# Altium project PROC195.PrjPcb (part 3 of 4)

## Sheet PROC195_DAC.SchDoc
size 431 x 279 mm; SheetNumber: 14; SheetTotal: 20
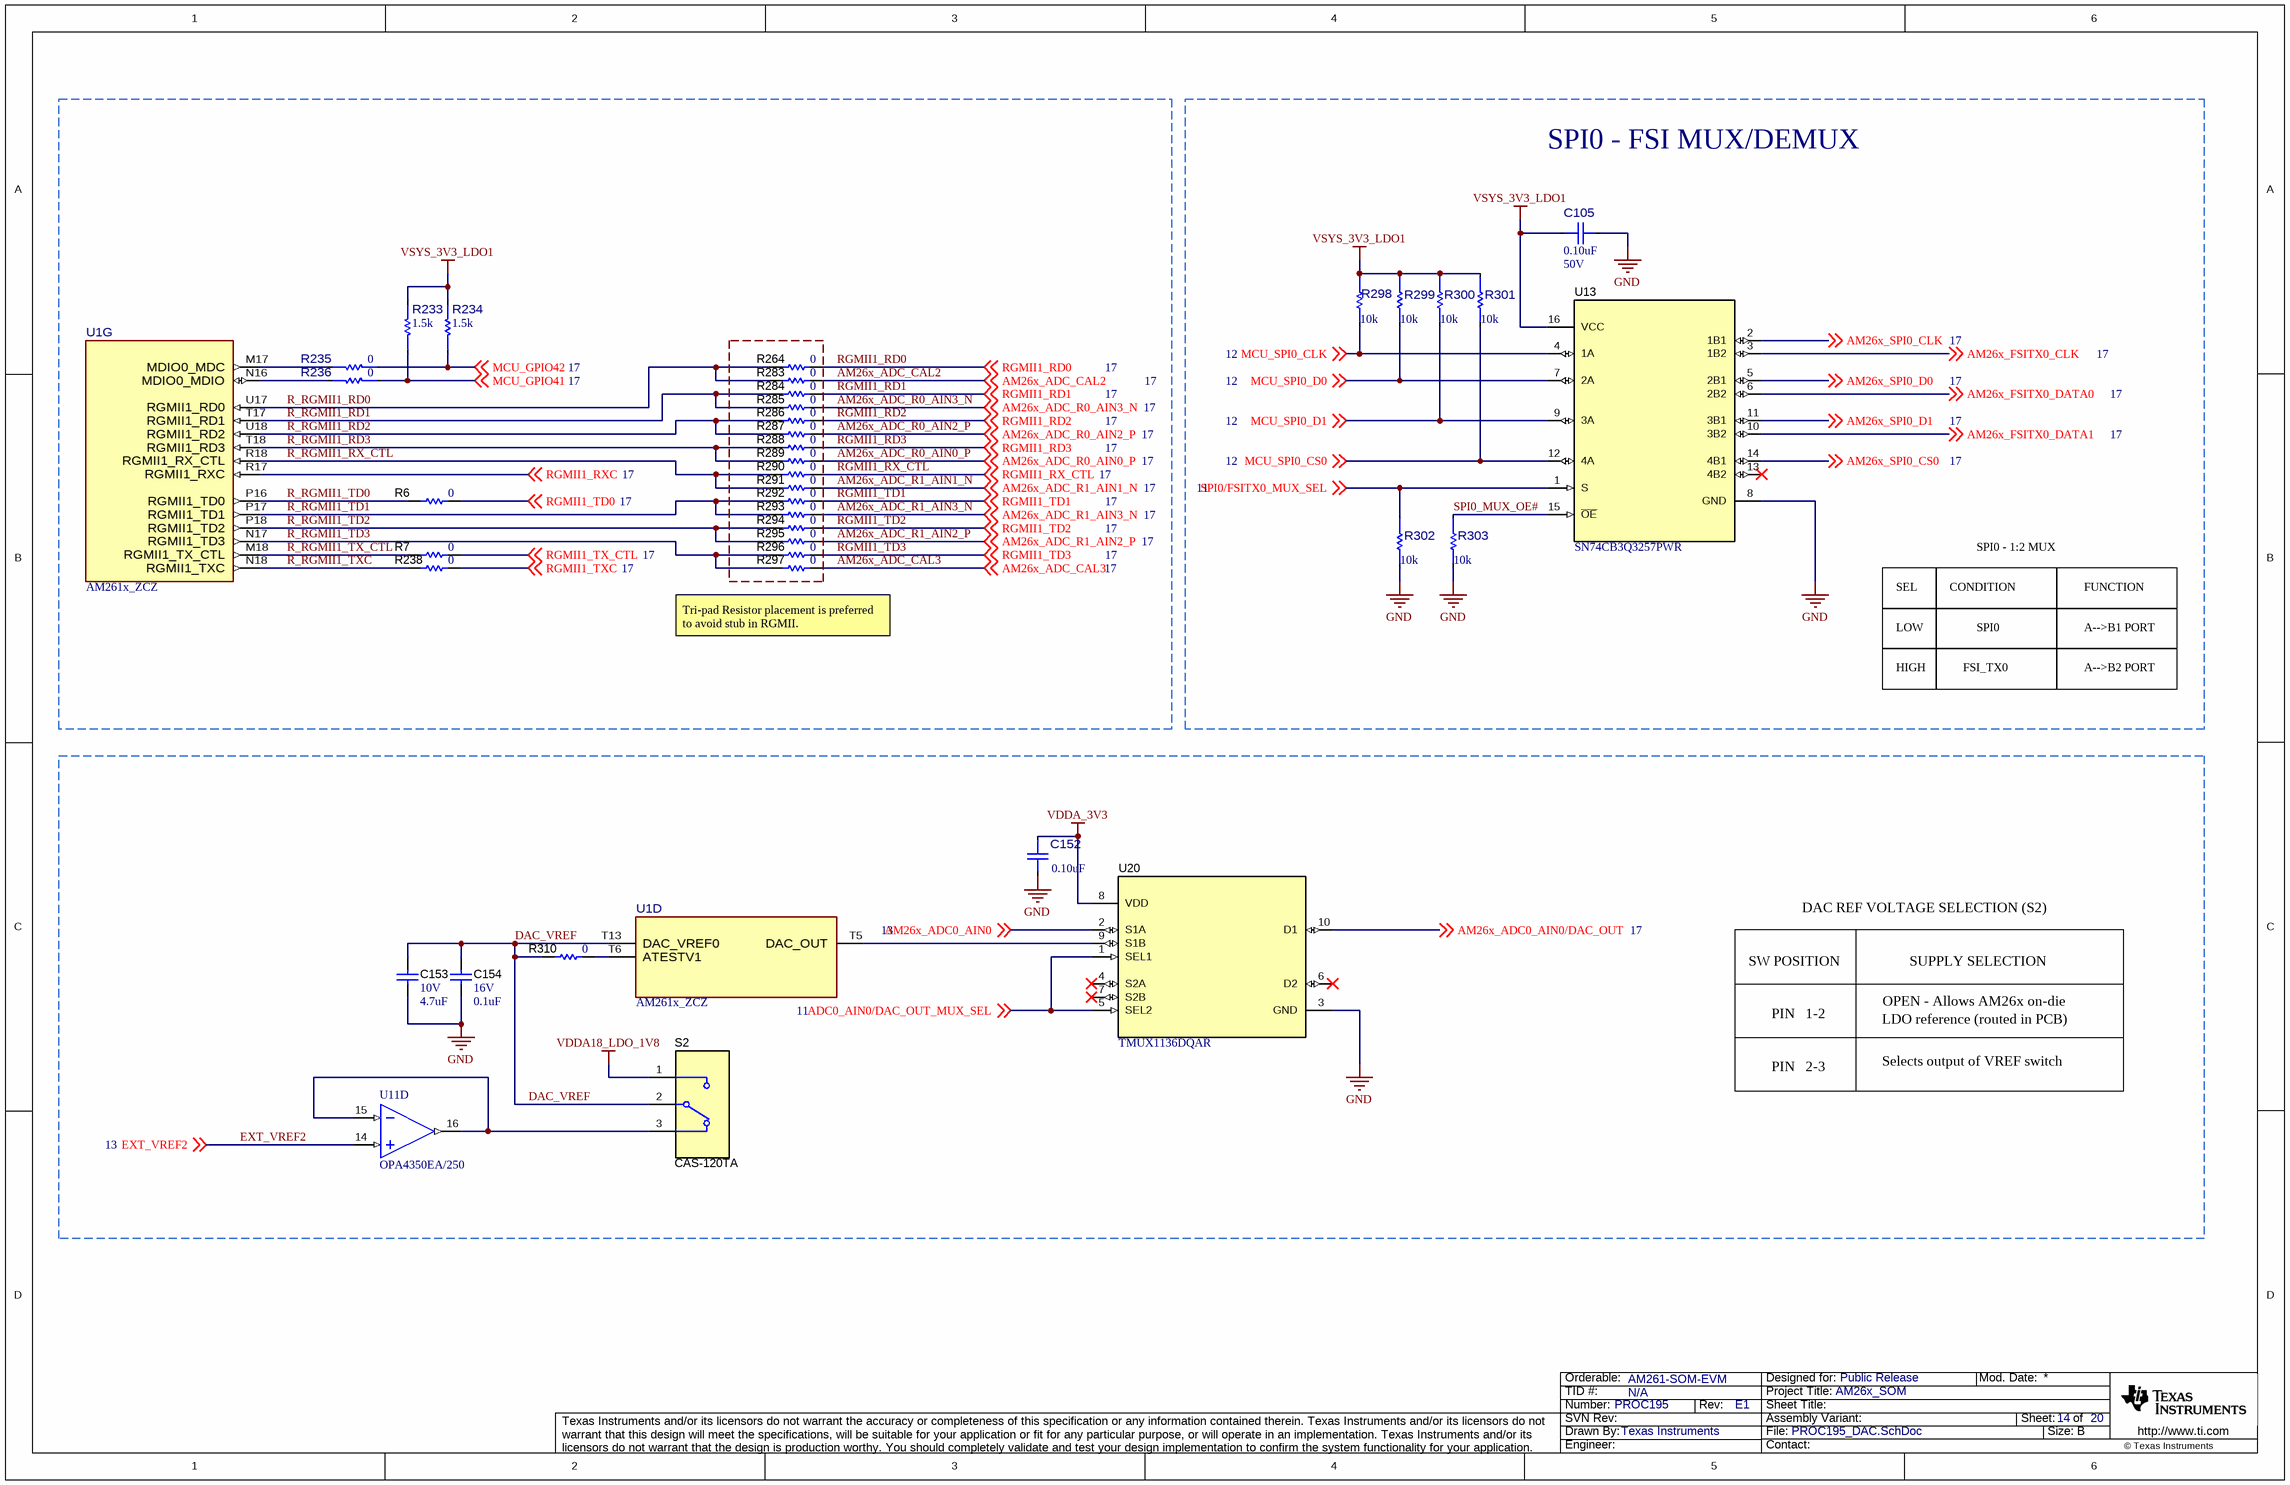
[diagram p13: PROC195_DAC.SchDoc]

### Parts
C105  ValueDisplayed: 0.10uF  VDC_V: 50V  [FP-GRM155R71H104KE14D_0402-MFG]  (hidden comment: GRM155R71H104KE14D)
C152  ValueDisplayed: 0.10uF  [FP-GRM155R71H104KE14D_0402-MFG]  (hidden comment: GRM155R71H104KE14D)
C153  VDC_V: 10V  ValueDisplayed: 4.7uF  [0402]  (hidden comment: GRM155R61A475MEAAD)
C154  VDC_V: 16V  ValueDisplayed: 0.1uF  [0201]  (hidden comment: GRM033Z71C104KE14D)
R6  ValueDisplayed: 0  [0201]  (hidden comment: ERJ-1GN0R00C)
R7  ValueDisplayed: 0  [0201]  (hidden comment: ERJ-1GN0R00C)
R233  value 1.5k  [FP-ERJ-2GEJ152X_0402-MFG]  (hidden comment: ERJ-2GEJ152X)
R234  value 1.5k  [FP-ERJ-2GEJ152X_0402-MFG]  (hidden comment: ERJ-2GEJ152X)
R235  value 0  [FP-ERJ-2GE0R00X_0402-MFG]  (hidden comment: ERJ-2GE0R00X)
R236  value 0  [FP-ERJ-2GE0R00X_0402-MFG]  (hidden comment: ERJ-2GE0R00X)
R238  ValueDisplayed: 0  [0201]  (hidden comment: ERJ-1GN0R00C)
R264  ValueDisplayed: 0  [0201]  (hidden comment: ERJ-1GN0R00C)
R283  ValueDisplayed: 0  [0201]  (hidden comment: ERJ-1GN0R00C)
R284  ValueDisplayed: 0  [0201]  (hidden comment: ERJ-1GN0R00C)
R285  ValueDisplayed: 0  [0201]  (hidden comment: ERJ-1GN0R00C)
R286  ValueDisplayed: 0  [0201]  (hidden comment: ERJ-1GN0R00C)
R287  ValueDisplayed: 0  [0201]  (hidden comment: ERJ-1GN0R00C)
R288  ValueDisplayed: 0  [0201]  (hidden comment: ERJ-1GN0R00C)
R289  ValueDisplayed: 0  [0201]  (hidden comment: ERJ-1GN0R00C)
R290  ValueDisplayed: 0  [0201]  (hidden comment: ERJ-1GN0R00C)
R291  ValueDisplayed: 0  [0201]  (hidden comment: ERJ-1GN0R00C)
R292  ValueDisplayed: 0  [0201]  (hidden comment: ERJ-1GN0R00C)
R293  ValueDisplayed: 0  [0201]  (hidden comment: ERJ-1GN0R00C)
R294  ValueDisplayed: 0  [0201]  (hidden comment: ERJ-1GN0R00C)
R295  ValueDisplayed: 0  [0201]  (hidden comment: ERJ-1GN0R00C)
R296  ValueDisplayed: 0  [0201]  (hidden comment: ERJ-1GN0R00C)
R297  ValueDisplayed: 0  [0201]  (hidden comment: ERJ-1GN0R00C)
R298  value 10k  [FP-RC0402JR-0710KL_0402-MFG]  (hidden comment: RC0402JR-0710KL)
R299  value 10k  [FP-RC0402JR-0710KL_0402-MFG]  (hidden comment: RC0402JR-0710KL)
R300  value 10k  [FP-RC0402JR-0710KL_0402-MFG]  (hidden comment: RC0402JR-0710KL)
R301  value 10k  [FP-RC0402JR-0710KL_0402-MFG]  (hidden comment: RC0402JR-0710KL)
R302  value 10k  [FP-RC0402JR-0710KL_0402-MFG]  (hidden comment: RC0402JR-0710KL)
R303  value 10k  [FP-RC0402JR-0710KL_0402-MFG]  (hidden comment: RC0402JR-0710KL)
R310  ValueDisplayed: 0  [0201]  (hidden comment: ERJ-1GN0R00C)
S2  CAS-120TA  [SW_CAS-120TA]
U1  AM261x_ZCZ  [ZCZ0324A-MFG]  (parts D,G of 13)
U11  OPA4350EA/250  [DBQ0016A_N]  (part D of 5)
U13  SN74CB3Q3257PWR  [PW0016A_L]
U20  TMUX1136DQAR  [DQA0010A]

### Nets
GND: C105.2 C152.2 C153.1 C154.1 R302.2 R303.2 U13.8(GND) U20.3(GND)
VDDA18_LDO_1V8: S2.1
VDDA_3V3: C152.1 U20.8(VDD)
VSYS_3V3_LDO1: C105.1 R233.2 R234.2 R298.1 R299.1 R300.1 R301.1 U13.16(VCC)
ADC0_AIN0/DAC_OUT_MUX_SEL: U20.1(SEL1) U20.5(SEL2) ; off-sheet ADC0_AIN0/DAC_OUT_MUX_SEL
AM26x_ADC0_AIN0: U20.2(S1A) ; off-sheet AM26x_ADC0_AIN0
AM26x_ADC0_AIN0/DAC_OUT: U20.10(D1) ; off-sheet AM26x_ADC0_AIN0/DAC_OUT
AM26x_ADC_CAL2: R283.2 ; off-sheet AM26x_ADC_CAL2
AM26x_ADC_CAL3: R297.2 ; off-sheet AM26x_ADC_CAL3
AM26x_ADC_R0_AIN0_P: R289.2 ; off-sheet AM26x_ADC_R0_AIN0_P
AM26x_ADC_R0_AIN2_P: R287.2 ; off-sheet AM26x_ADC_R0_AIN2_P
AM26x_ADC_R0_AIN3_N: R285.2 ; off-sheet AM26x_ADC_R0_AIN3_N
AM26x_ADC_R1_AIN1_N: R291.2 ; off-sheet AM26x_ADC_R1_AIN1_N
AM26x_ADC_R1_AIN2_P: R295.2 ; off-sheet AM26x_ADC_R1_AIN2_P
AM26x_ADC_R1_AIN3_N: R293.2 ; off-sheet AM26x_ADC_R1_AIN3_N
AM26x_FSITX0_CLK: U13.3(1B2) ; off-sheet AM26x_FSITX0_CLK
AM26x_FSITX0_DATA0: U13.6(2B2) ; off-sheet AM26x_FSITX0_DATA0
AM26x_FSITX0_DATA1: U13.10(3B2) ; off-sheet AM26x_FSITX0_DATA1
AM26x_SPI0_CLK: U13.2(1B1) ; off-sheet AM26x_SPI0_CLK
AM26x_SPI0_CS0: U13.14(4B1) ; off-sheet AM26x_SPI0_CS0
AM26x_SPI0_D0: U13.5(2B1) ; off-sheet AM26x_SPI0_D0
AM26x_SPI0_D1: U13.11(3B1) ; off-sheet AM26x_SPI0_D1
DAC_VREF: C153.2 C154.2 R310.1 S2.2 U1.T13(DAC_VREF0)
EXT_VREF2: U11.14(IN_D+) ; off-sheet EXT_VREF2
MCU_GPIO41: R233.1 R236.1 ; off-sheet MCU_GPIO41
MCU_GPIO42: R234.1 R235.1 ; off-sheet MCU_GPIO42
MCU_SPI0_CLK: R298.2 U13.4(1A) ; off-sheet MCU_SPI0_CLK
MCU_SPI0_CS0: R301.2 U13.12(4A) ; off-sheet MCU_SPI0_CS0
MCU_SPI0_D0: R299.2 U13.7(2A) ; off-sheet MCU_SPI0_D0
MCU_SPI0_D1: R300.2 U13.9(3A) ; off-sheet MCU_SPI0_D1
R_RGMII1_RD0: R264.1 R283.1 U1.U17(RGMII1_RD0)
R_RGMII1_RD1: R284.1 R285.1 U1.T17(RGMII1_RD1)
R_RGMII1_RD2: R286.1 R287.1 U1.U18(RGMII1_RD2)
R_RGMII1_RD3: R288.1 R289.1 U1.T18(RGMII1_RD3)
R_RGMII1_RX_CTL: R290.1 R291.1 U1.R18(RGMII1_RX_CTL)
R_RGMII1_TD0: R6.1 U1.P16(RGMII1_TD0)
R_RGMII1_TD1: R292.1 R293.1 U1.P17(RGMII1_TD1)
R_RGMII1_TD2: R294.1 R295.1 U1.P18(RGMII1_TD2)
R_RGMII1_TD3: R296.1 R297.1 U1.N17(RGMII1_TD3)
R_RGMII1_TX_CTL: R7.1 U1.M18(RGMII1_TX_CTL)
R_RGMII1_TXC: R238.1 U1.N18(RGMII1_TXC)
RGMII1_RD0: R264.2 ; off-sheet RGMII1_RD0
RGMII1_RD1: R284.2 ; off-sheet RGMII1_RD1
RGMII1_RD2: R286.2 ; off-sheet RGMII1_RD2
RGMII1_RD3: R288.2 ; off-sheet RGMII1_RD3
RGMII1_RX_CTL: R290.2 ; off-sheet RGMII1_RX_CTL
RGMII1_RXC: U1.R17(RGMII1_RXC) ; off-sheet RGMII1_RXC
RGMII1_TD0: R6.2 ; off-sheet RGMII1_TD0
RGMII1_TD1: R292.2 ; off-sheet RGMII1_TD1
RGMII1_TD2: R294.2 ; off-sheet RGMII1_TD2
RGMII1_TD3: R296.2 ; off-sheet RGMII1_TD3
RGMII1_TX_CTL: R7.2 ; off-sheet RGMII1_TX_CTL
RGMII1_TXC: R238.2 ; off-sheet RGMII1_TXC
SPI0/FSITX0_MUX_SEL: R302.1 U13.1(S) ; off-sheet SPI0/FSITX0_MUX_SEL
SPI0_MUX_OE#: R303.1 U13.15(~{OE})
NetR235_2: R235.2 U1.M17(MDIO0_MDC)
NetR236_2: R236.2 U1.N16(MDIO0_MDIO)
NetR310_2: R310.2 U1.T6(ATESTV1)
NetS2_3: S2.3 U11.15(IN_D-) U11.16(OUT_D)
NetU1_T5: U1.T5(DAC_OUT) U20.9(S1B)

Not connected (* = marked no-connect by the designer): U13 13(4B2)*; U20 4(S2A)* 6(D2)* 7(S2B)*

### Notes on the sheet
- SPI0 - FSI MUX/DEMUX
- SPI0 - 1:2 MUX
- Tri-pad Resistor placement is preferred to avoid stub in RGMII.
- SEL
- LOW
- CONDITION
- SPI0
- FUNCTION
- A-->B1 PORT
- HIGH
- FSI_TX0
- A-->B2 PORT
- SW POSITION
- DAC REF VOLTAGE SELECTION (S2)
- SUPPLY SELECTION
- PIN   1-2
- LDO reference (routed in PCB)
- OPEN - Allows AM26x on-die
- PIN   2-3
- Selects output of VREF switch

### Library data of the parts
C105 C152 = CMP-0096855-1: Chip Multilayer Ceramic Capacitors for General Purpose, 0402, 0.10uF, X7R, 15%, 10%, 50V; Manufacturer: Murata; SizeZ_mm: 0.55mm; Value: 100nF; AEC Qualified: No
C153 = CMP-0006582-2: CAP, CERM, 4.7 uF, 10 V, +/- 20%, X5R, 0402; Manufacturer: MuRata; TaMin_C: -55°C; Polarized: N; SizeAreaWB_mm2: 3; Value1: Unknown; U/M: EA; Value: 4.7uF; TaMax_C: 85°C; SizeZ_mm: 0.6; SizeX_mm: 1; SizeY_mm: 0.5; Cap_F: 4.7µF; AEC Category: Q200
C154 = CMP-0064970-1: CAP, CERM, 0.1 uF, 16 V,+/- 10%, X7R, 0201; Manufacturer: MuRata; TaMin_C: -55°C; Polarized: N; SizeAreaWB_mm2: 2.08; Value1: Unknown; U/M: EA; Value: 0.1uF; TaMax_C: 125°C; SizeZ_mm: 0.26; SizeX_mm: 0.6; SizeY_mm: 0.3; SizeArea_mm2: 0.18; Cap_F: 100nF; AEC Category: Q200
R6 R7 R238 R264 R283-R297 R310 = CMP-0065361-1: RES, 0, 5%, .05 W, AEC-Q200 Grade 0, 0201; Manufacturer: Panasonic; Power_W: 50mW; Green_Lifecycle: Not Set; TempCo: ppm/C; Value_Code: 0000; Green_REACh: Incomplete; U/M: EA; Value: 0; EIA_Code: E24; SizeX_mm: 0.6; SizeY_mm: 0.3; SizeZ_mm: 0.26; Value2: .05W; SizeArea_mm2: 0.18; AEC Qualified: Y; AEC Category: Q200
R233 R234 = CMP-0042990-1: Res Thick Film 0402 1.5K Ohm 5% 1/10W ±200ppm/°C Molded SMD Punched Carrier T/R; Manufacturer: Panasonic; AEC Grade: Grade 0; AEC Qualified: Yes; Power_W: 100mW; SizeZ_mm: 0.4mm; VDC_V: 50V; Category 5A00970A6D5C81C7: Uncategorized; Category 5C6A91606D4187Ad: Resistors; Category 7542B8484461Ae85: Passive Components; Category Cd01000Bfc2916C6: Single Components
R235 R236 = CMP-0002710-1: 0 Ohms Jumper Chip Resistor 0402 (1005 Metric) Automotive AEC-Q200 Thick Film; Manufacturer: Panasonic; AEC Grade: Grade 0; AEC Qualified: Yes; SizeZ_mm: 0.4mm; Power: 100mW
R298-R303 = CMP-0094798-1: Res Thick Film 0402 10K Ohm 5% 0.063W(1/16W) ±100ppm/C Pad SMD T/R; Manufacturer: YAGEO; AEC Qualified: No; Category Cd01000Bfc2916C6: Single Components; SizeZ_mm: 0.4mm; VDC_V: 50V; Category 5C6A91606D4187Ad: Resistors; TempCo: 100ppm/°C; Power_W: 63mW; Category 7542B8484461Ae85: Passive Components
S2 = CMP-0002139-2: Switch, Slide, SPDT  100mA, SMT; Manufacturer: Copal Electronics; CurrentRating_mA: 100A; SwitchFunction: On-On; VDC_V: 6V; PositionCount: 1
U1 = CMP-0121930-1: Manufacturer: Texas Instruments; SizeZ_mm: 1.4mm; Standoff Height: 0.35mm
U11 = CMP-0041147-1: High-Speed, Single-Supply, Rail-to-Rail Operational Amplifier MicroAmplifier(TM) Series, 2.7 to 5.5 V, -55 to 150 degC, 16-pin SOP (DBQ16), Green (RoHS & no Sb/Br); Manufacturer: Texas Instruments; Number of Channels: 4; Vio (25C)(Max)(mV): 0.5; Total Supply Voltage(Min)(+5V is 5, +/-5V is 10): 2.7; Slew Rate(Typ)(V/us): 22; Total Supply Voltage(Max)(+5V is 5, +/-5V is 10): 5.5; Iq per channel(Max)(mA): 7.5; Vn at 1kHz(Typ)(nV/rtHz): 18; Sub Family: Low Input Bias Current Amp (<=10pA), Low Offset Voltage Amplifier (<=500uV), Low Supply Voltage Amplifier (<=2.7V), Precision Amplifier; IIB(Max)(pA): 10; CMRR(Min)(dB): 66
U13 = CMP-0076540-1: 4-Bit One-of-2 FET Multiplexer/Demultiplexer 2.5-V/3.3-V Low-Voltage, High-Bandwidth Bus Switch, PW0016A (TSSOP-16); Manufacturer: Texas Instruments; SizeAreaWB_mm2: 58.8; SizeArea_mm2: 32.0; SizeZ_mm: 1.2; SizeY_mm: 5.0; U/M: EA; CompType: IC; SizeX_mm: 6.4
U20 = CMP-0860454-1: 5-V Low-Leakage-Current, 2:1, 2-Channel Precision Analog Switch, DQA0010A (USON-10); Manufacturer: Texas Instruments; SizeZ_mm: 0.55; SizeX_mm: 1; AEC Category: Q200; SizeArea_mm2: 2.5; AEC Qualified: N; SizeAreaWB_mm2: 7; Rating: Catalog; CompType: IC

## Sheet PROC195_CLK_LED_CURRENT_MON_TEMP_CONN.SchDoc
size 431 x 279 mm; DocumentNumber: 7; SheetNumber: 15; SheetTotal: 20; PageSetup: Record=PageOptions¦CenterHorizontal=True¦CenterVertical=True¦PrintScale=1.00¦XCorrection=1.00¦YCorrection=1.00¦PrintKind=0¦BorderSize=5000000¦LeftOffset=0¦BottomOffset=0¦Orientation=2¦PaperLength=1000¦PaperWidth=1000¦Scale=100¦PaperSource=15¦PrintQuality=600¦MediaType=1¦DitherType=10¦PaperKind=Letter¦PrintScaleMode=1
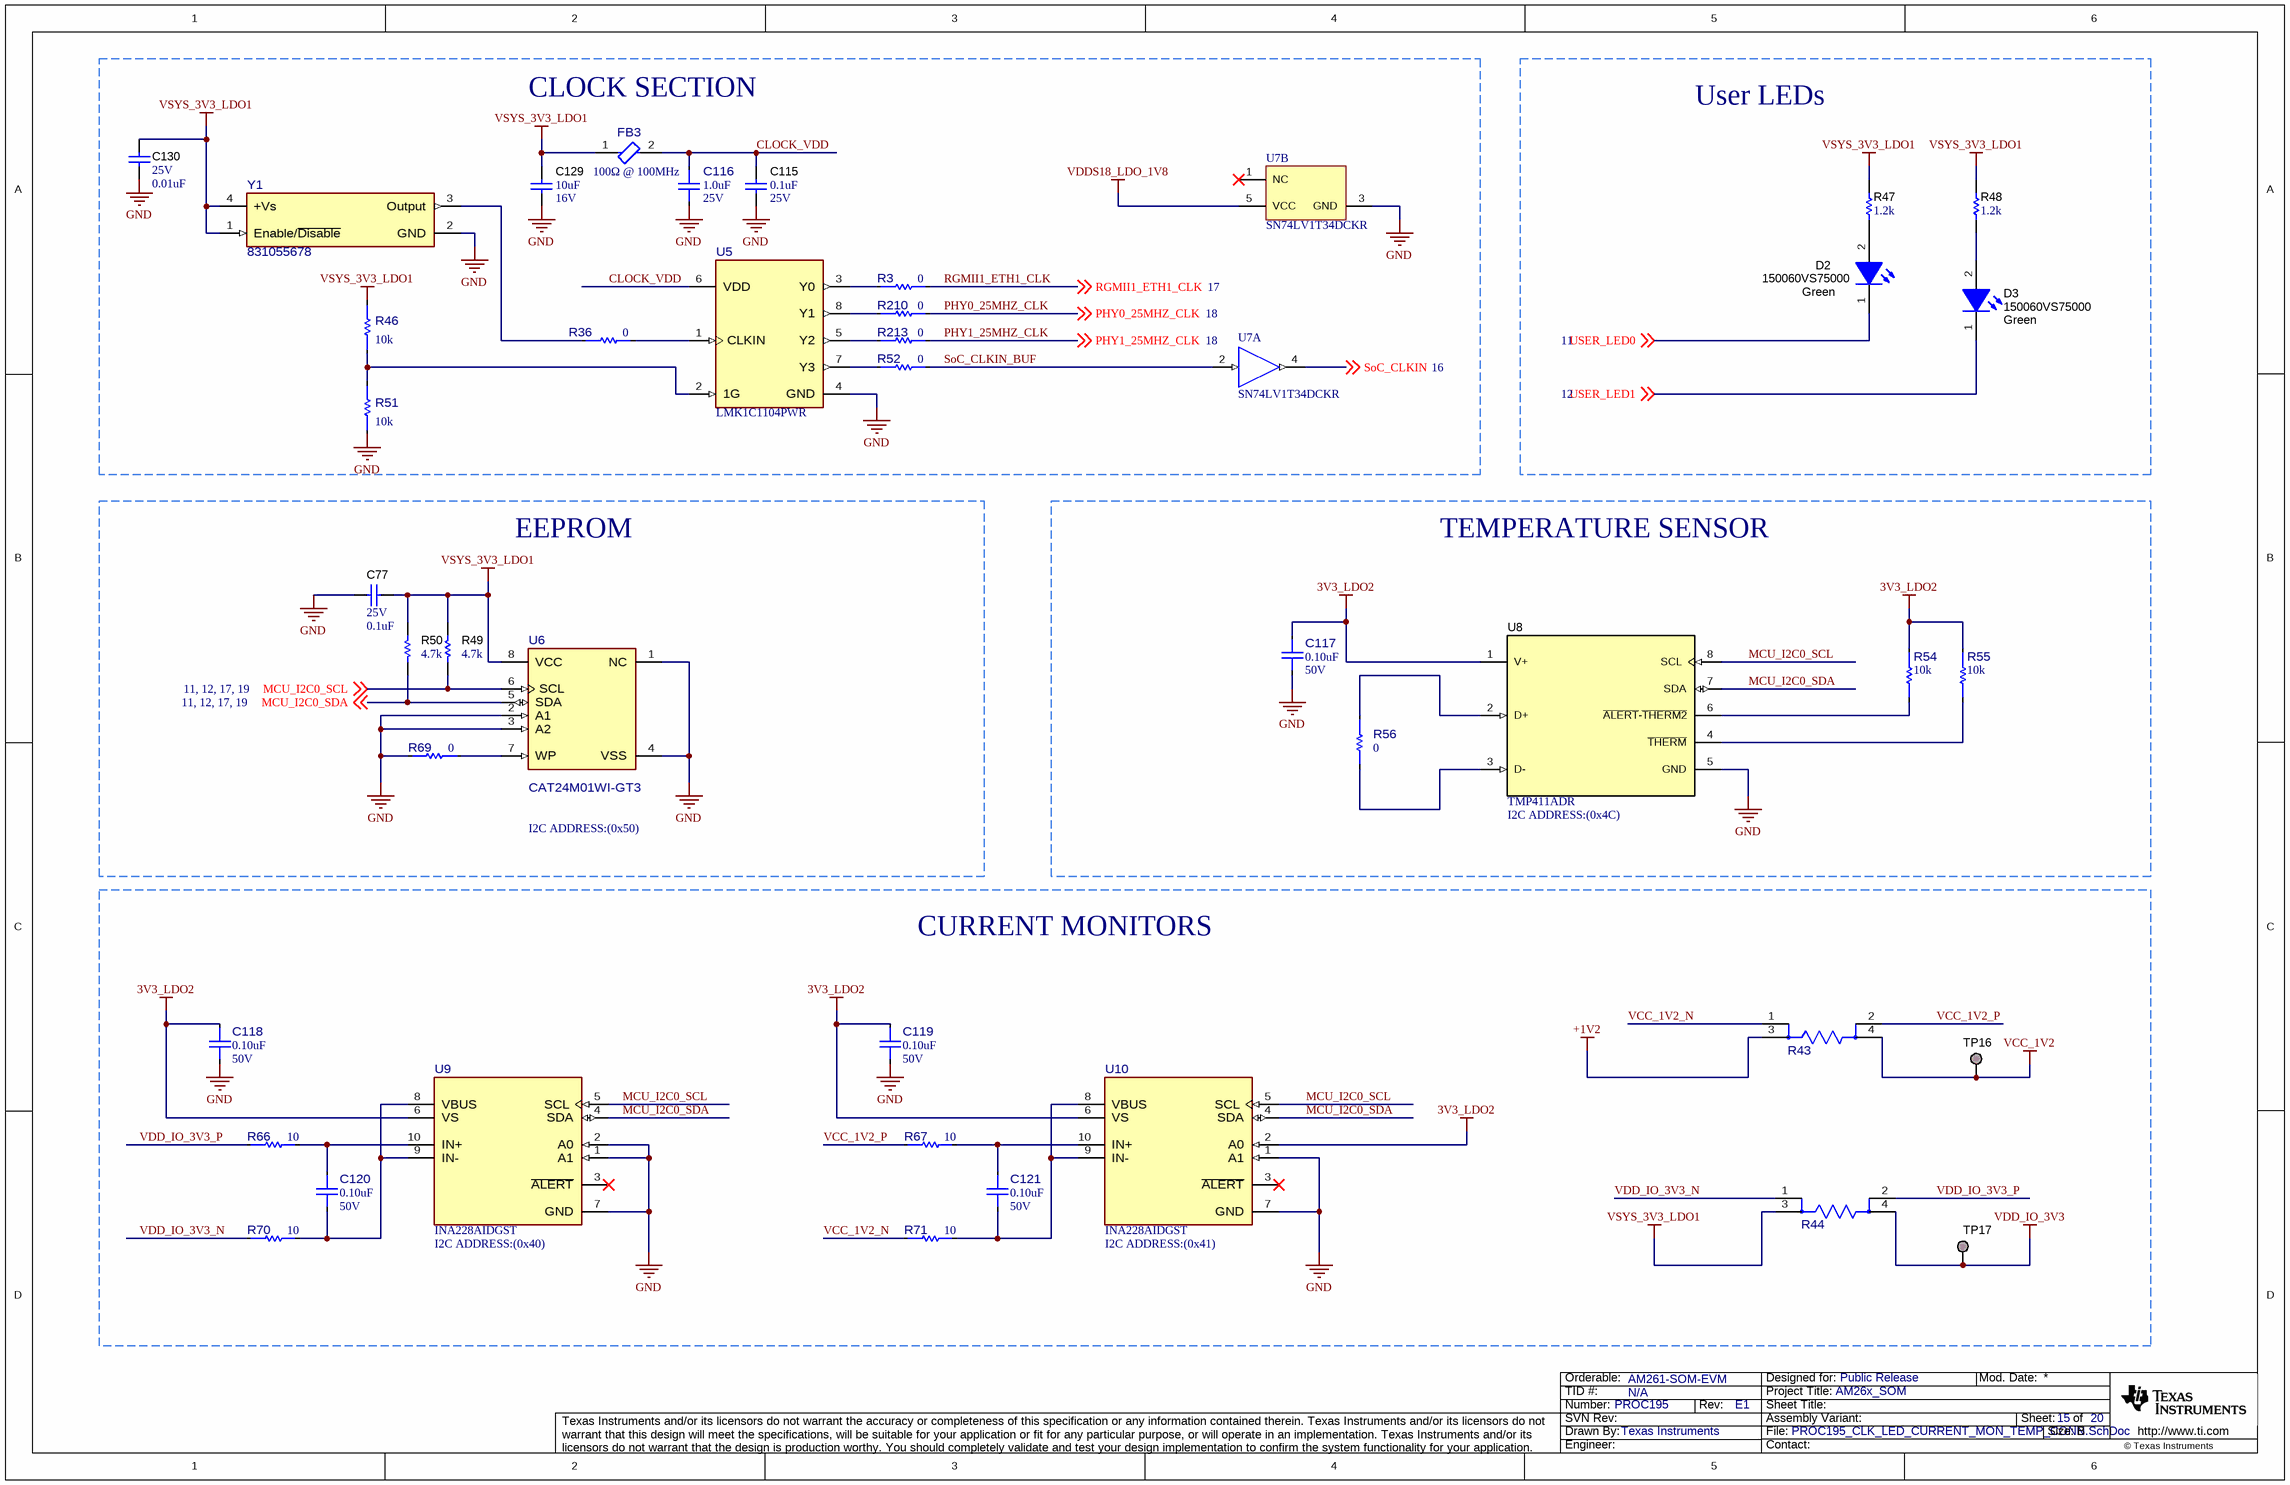
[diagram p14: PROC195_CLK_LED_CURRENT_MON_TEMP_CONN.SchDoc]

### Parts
C77  VDC_V: 25V  ValueDisplayed: 0.1uF  [0402]  (hidden comment: GRM155R71E104KE14D)
C115  VDC_V: 25V  ValueDisplayed: 0.1uF  [0402]  (hidden comment: GRM155R71E104KE14D)
C116  ValueDisplayed: 1.0uF  VDC_V: 25V  [FP-GRM155C81E105KE11D_0402-MFG]  (hidden comment: GRM155C81E105KE11D)
C117  ValueDisplayed: 0.10uF  VDC_V: 50V  [FP-GRM155R71H104KE14D_0402-MFG]  (hidden comment: GRM155R71H104KE14D)
C118  ValueDisplayed: 0.10uF  VDC_V: 50V  [FP-GRM155R71H104KE14D_0402-MFG]  (hidden comment: GRM155R71H104KE14D)
C119  ValueDisplayed: 0.10uF  VDC_V: 50V  [FP-GRM155R71H104KE14D_0402-MFG]  (hidden comment: GRM155R71H104KE14D)
C120  ValueDisplayed: 0.10uF  VDC_V: 50V  [FP-GRM155R71H104KE14D_0402-MFG]  (hidden comment: GRM155R71H104KE14D)
C121  ValueDisplayed: 0.10uF  VDC_V: 50V  [FP-GRM155R71H104KE14D_0402-MFG]  (hidden comment: GRM155R71H104KE14D)
C129  VDC_V: 16V  ValueDisplayed: 10uF  [0603]  (hidden comment: GRM188R61C106MAALD)
C130  VDC_V: 25V  ValueDisplayed: 0.01uF  [0402]  (hidden comment: GCM155R71E103KA37D)
D2  150060VS75000  value Green  [WL-SMCW_GREEN]
D3  150060VS75000  value Green  [WL-SMCW_GREEN]
FB3  Impedance At Frequency: 100Ω @ 100MHz  [FP-BLM18EG101TN1D_0603-MFG]  (hidden comment: BLM18EG101TN1D)
R3  value 0  [FP-ERJ-2GE0R00X_0402-MFG]  (hidden comment: ERJ-2GE0R00X)
R36  value 0  [FP-ERJ-2GE0R00X_0402-MFG]  (hidden comment: ERJ-2GE0R00X)
R43  FC4L16R010FER  [FP-FC4L16R010FER_0306-MFG]  (value not drawn)
R44  FC4L16R010FER  [FP-FC4L16R010FER_0306-MFG]  (value not drawn)
R46  value 10k  [FP-RC0402JR-0710KL_0402-MFG]  (hidden comment: RC0402JR-0710KL)
R47  ValueDisplayed: 1.2k  [0402]  (hidden comment: CRCW04021K20JNED)
R48  ValueDisplayed: 1.2k  [0402]  (hidden comment: CRCW04021K20JNED)
R49  value 4.7k  [0402]  (hidden comment: CRCW04024K70JNED)
R50  value 4.7k  [0402]  (hidden comment: CRCW04024K70JNED)
R51  value 10k  [FP-RC0402JR-0710KL_0402-MFG]  (hidden comment: RC0402JR-0710KL)
R52  value 0  [FP-ERJ-2GE0R00X_0402-MFG]  (hidden comment: ERJ-2GE0R00X)
R54  value 10k  [FP-RC0402JR-0710KL_0402-MFG]  (hidden comment: RC0402JR-0710KL)
R55  value 10k  [FP-RC0402JR-0710KL_0402-MFG]  (hidden comment: RC0402JR-0710KL)
R56  value 0  [FP-ERJ-2GE0R00X_0402-MFG]  (hidden comment: ERJ-2GE0R00X)
R66  value 10  [FP-RC0402FR-0710RL_0402-MFG]  (hidden comment: RC0402FR-0710RL)
R67  value 10  [FP-RC0402FR-0710RL_0402-MFG]  (hidden comment: RC0402FR-0710RL)
R69  value 0  [FP-ERJ-2GE0R00X_0402-MFG]  (hidden comment: ERJ-2GE0R00X)
R70  value 10  [FP-RC0402FR-0710RL_0402-MFG]  (hidden comment: RC0402FR-0710RL)
R71  value 10  [FP-RC0402FR-0710RL_0402-MFG]  (hidden comment: RC0402FR-0710RL)
R210  value 0  [FP-ERJ-2GE0R00X_0402-MFG]  (hidden comment: ERJ-2GE0R00X)
R213  value 0  [FP-ERJ-2GE0R00X_0402-MFG]  (hidden comment: ERJ-2GE0R00X)
TP16  TESTPOINT  [TP_25MIL-SMT]  (value not drawn)  (no BOM)
TP17  TESTPOINT  [TP_25MIL-SMT]  (value not drawn)  (no BOM)
U5  LMK1C1104PWR  [PW0008A-MFG]
U6  CAT24M01WI-GT3  [FP-CAT24M01WI-GT3_SOIC8-IPC_C]
U7  SN74LV1T34DCKR  [DCK0005A_N]  (parts A,B of 2)
U8  TMP411ADR  [D0008A_N]
U9  INA228AIDGST  [DGS0010A-MFG]
U10  INA228AIDGST  [DGS0010A-MFG]
Y1  831055678  [FP-831055678_SMT_OSC_3MM2_2MM5-MFG]

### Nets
3V3_LDO2: C117.1 C118.1 C119.1 R54.1 R55.1 U8.1(V+) U9.6(VS) U10.2(A0) U10.6(VS)
+1V2: R43.3(1_I)
GND: C77.2 C115.2 C116.2 C117.2 C118.2 C119.2 C129.2 C130.1 R51.1 R69.2 U5.4(GND) U6.1(NC) U6.2(A1) U6.3(A2) U6.4(VSS) U7.3(GND) U8.5(GND) U9.1(A1) U9.2(A0) U9.7(GND) U10.1(A1) U10.7(GND) Y1.2(GND)
VCC_1V2: R43.4(2_I) TP16.1
VDD_IO_3V3: R44.4(2_I) TP17.1
VDDS18_LDO_1V8: U7.5(VCC)
VSYS_3V3_LDO1: C77.1 C129.1 C130.2 FB3.1 R44.3(1_I) R46.2 R47.2 R48.2 R49.2 R50.2 U6.8(VCC) Y1.1(Enable/~{Disable}) Y1.4(+Vs)
CLOCK_VDD: C115.1 C116.1 FB3.2 U5.6(VDD)
MCU_I2C0_SCL: R49.1 U6.6(SCL) U8.8(SCL) U9.5(SCL) U10.5(SCL) ; off-sheet MCU_I2C0_SCL
MCU_I2C0_SDA: R50.1 U6.5(SDA) U8.7(SDA) U9.4(SDA) U10.4(SDA) ; off-sheet MCU_I2C0_SDA
PHY0_25MHZ_CLK: R210.2 ; off-sheet PHY0_25MHZ_CLK
PHY1_25MHZ_CLK: R213.2 ; off-sheet PHY1_25MHZ_CLK
RGMII1_ETH1_CLK: R3.2 ; off-sheet RGMII1_ETH1_CLK
SoC_CLKIN: U7.4(Y) ; off-sheet SoC_CLKIN
SoC_CLKIN_BUF: R52.2 U7.2(A)
USER_LED0: D2.1(K) ; off-sheet USER_LED0
USER_LED1: D3.1(K) ; off-sheet USER_LED1
VCC_1V2_N: R43.1(1_V) R71.1
VCC_1V2_P: R43.2(2_V) R67.1
VDD_IO_3V3_N: R44.1(1_V) R70.1
VDD_IO_3V3_P: R44.2(2_V) R66.1
NetC120_1: C120.1 R66.2 U9.10(IN+)
NetC120_2: C120.2 R70.2 U9.8(VBUS) U9.9(IN-)
NetC121_1: C121.1 R67.2 U10.10(IN+)
NetC121_2: C121.2 R71.2 U10.8(VBUS) U10.9(IN-)
NetD2_2: D2.2(A) R47.1
NetD3_2: D3.2(A) R48.1
NetR3_1: R3.1 U5.3(Y0)
NetR36_1: R36.1 Y1.3(Output)
NetR36_2: R36.2 U5.1(CLKIN)
NetR46_1: R46.1 R51.2 U5.2(1G)
NetR52_1: R52.1 U5.7(Y3)
NetR54_2: R54.2 U8.6(~{ALERT}-~{THERM2})
NetR55_2: R55.2 U8.4(~{THERM})
NetR56_1: R56.1 U8.2(D+)
NetR56_2: R56.2 U8.3(D-)
NetR69_1: R69.1 U6.7(WP)
NetR210_1: R210.1 U5.8(Y1)
NetR213_1: R213.1 U5.5(Y2)

Not connected (* = marked no-connect by the designer): U7 1(NC)*; U9 3(~{ALERT})*; U10 3(~{ALERT})*

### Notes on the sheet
- CLOCK SECTION
- User LEDs
- EEPROM
- TEMPERATURE SENSOR
- I2C ADDRESS:(0x50)
- (near U8) I2C ADDRESS:(0x4C)
- CURRENT MONITORS
- (near U9) I2C ADDRESS:(0x40)
- (near U10) I2C ADDRESS:(0x41)

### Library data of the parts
C77 C115 = CMP-0006659-2: CAP, CERM, 0.1 uF, 25 V, +/- 10%, X7R, 0402; Manufacturer: MuRata; TaMin_C: -55°C; Polarized: N; SizeAreaWB_mm2: 3; Value1: Unknown; U/M: EA; Value: 0.1uF; TaMax_C: 125°C; SizeZ_mm: 0.6; SizeX_mm: 1; SizeY_mm: 0.5; Cap_F: 100nF; AEC Category: Q200
C116 = CMP-0121658-2: Chip Multilayer Ceramic Capacitors for General Purpose, 0402, 1.0uF, X6S, 22%, 10%, 25V; Manufacturer: Murata; AEC Qualified: No; Cap_F: 1µF; SizeZ_mm: 0.6mm; Value: 1µF
C117-C121 = CMP-0096855-1: as C105 on sheet PROC195_DAC
C129 = CMP-0007336-5: CAP, CERM, 10 uF, 16 V, +/- 20%, X5R, 0603; Manufacturer: MuRata; TaMin_C: -55°C; Polarized: N; SizeAreaWB_mm2: 4.68; Value1: Unknown; U/M: EA; Value: 10uF; TaMax_C: 85°C; SizeZ_mm: 1; SizeX_mm: 1.6; SizeY_mm: 0.8; SizeArea_mm2: 1.28; Cap_F: 10µF; AEC Category: Q200
C130 = CMP-0006352-2: CAP, CERM, 0.01 uF, 25 V, +/- 10%, X7R, 0402; Manufacturer: MuRata; TaMin_C: -55°C; Polarized: N; SizeAreaWB_mm2: 3; Value1: Unknown; U/M: EA; Value: 0.01uF; TaMax_C: 125°C; SizeZ_mm: 0.6; SizeX_mm: 1; SizeY_mm: 0.5; Cap_F: 10nF; AEC Category: Q200
D2 D3 = CMP-0002894-2: LED, Green, SMD; Manufacturer: Wurth Elektronik; Io_A: 20mA; Value1: W; Vf_V: 2V; Type: AlInGaP
FB3 = CMP-0122093-1: Chip Ferrite Bead, 0603, 100Ω @ 100MHz, 25%, 0.045Ω, 2A; Manufacturer: Murata; DCR_ohm: 45m; SizeZ_mm: 0.65mm; AEC Qualified: No
R3 R36 R52 R56 R69 R210 R213 = CMP-0002710-1: 0 Ohms Jumper Chip Resistor 0402 (1005 Metric) Automotive AEC-Q200 Thick Film; Manufacturer: Panasonic; SizeZ_mm: 0.4mm; AEC Qualified: Yes; AEC Grade: Grade 0; Power: 100mW
R43 R44 = CMP-0122058-1: Res Metal Foil 0306 0.01 Ohm 1% 0.25W(1/4W) ±50ppm/C Epoxy Resin Wide Terminal SMD T/R; Manufacturer: Ohmite; AEC Qualified: No; Power_W: 250mW; Res_ohm: 10m; SizeZ_mm: 0.7mm; TempCo: 50ppm/°C; Value: 10m
R46 R51 = CMP-0094798-1: Res Thick Film 0402 10K Ohm 5% 0.063W(1/16W) ±100ppm/C Pad SMD T/R; Manufacturer: YAGEO; Power_W: 63mW; TempCo: 100ppm/°C; SizeZ_mm: 0.4mm; AEC Qualified: No; VDC_V: 50V; Category Cd01000Bfc2916C6: Single Components; Category 5C6A91606D4187Ad: Resistors; Category 7542B8484461Ae85: Passive Components
R47 R48 = CMP-0026854-5: RES, 1.2 k, 5%, 0.063 W, AEC-Q200 Grade 0, 0402; Manufacturer: Vishay-Dale; Power_W: 63mW; TempCo: 200 ppm/C; Value_Code: 1k20; Value: 1.2k; EIA_Code: E24; SizeX_mm: 1; SizeY_mm: 0.5; SizeZ_mm: 0.6; Value2: 0.063W; AEC Qualified: Y; VDC_V: 50V; AEC Category: Q200; AEC Grade: 0
R49 R50 = CMP-0026938-5: RES, 4.7 k, 5%, 0.063 W, AEC-Q200 Grade 0, 0402; Manufacturer: Vishay-Dale; Power_W: 63mW; TempCo: 200 ppm/C; Value_Code: 4k70; SizeX_mm: 1; SizeY_mm: 0.5; SizeZ_mm: 0.6; Value2: 0.063W; AEC Qualified: Y; AEC Grade: 0; AEC Category: Q200; EIA_Code: E24; VDC_V: 50V
R54 R55 = CMP-0094798-1: as R298-R303 on sheet PROC195_DAC
R66 R67 R70 R71 = CMP-0122043-1: Res General Purpose Thick Film 0402 10 Ohm 1% 1/16W ±200ppm/°C Molded SMD Paper T/R; Manufacturer: Yageo; AEC Qualified: No; Power_W: 63mW; SizeZ_mm: 0.4mm; VDC_V: 50V
TP16 TP17 = CMP-0078143-3: TEST POINT.  No entry in BOM.
U5 = CMP-0096980-1: 1.8-V, 2.5-V, and 3.3-V LVCMOS Clock Buffer Family; Manufacturer: Texas Instruments; Logic Function: Non-Inverting; TaMax_C: +125°C; TJmax_C: +150°C; Max Supply Voltage: 3.465V; Number Of Elements: 5; TaMin_C: -40°C; Nominal Supply Current: 25-33000uA; Number Of Outputs: 4; Number Of Inputs: 1; AEC Qualified: No; Min Supply Voltage: 1.71V; SizeZ_mm: 1.2mm; Standoff Height: 0.05mm; Propagation Delay: 1.5ns
U6 = CMP-0122130-1: EEPROM Serial-I2C 1M-bit 128K x 8 2.5V/3.3V/5V 8-Pin SOIC N T/R; Manufacturer: ON Semi; SizeZ_mm: 1.75mm; Access Time: 0.4us; AEC Qualified: No; Frequency_Fixed: 1MHz; Interface: I2C; Max Supply Voltage: 5.5V; Memory Size: 1Mbits; Min Supply Voltage: 1.8V; Nominal Supply Current: 1-5mA; Standoff Height: 0.1mm; TaMax_C: +85°C; TaMin_C: -40°C; TJmax_C: +150°C
U7 = CMP-0051718-3: Single Power Supply BUFFER Logic Level Shifter (no enable), DCK0005A (SOT-SC70-5); Manufacturer: Texas Instruments; 3-State Output: Yes; Sub-Family: Non-Inverting Buffer/Driver; Rating: Catalog; ICC @ Nom Voltage(Max)(mA): 0.01; Logic: True; tpd @ Nom Voltage(Max)(ns): 14.5,9.5,8.0,6.5; Output Type: CMOS; VCC(Max)(V): 5.5; Voltage(Nom)(V): 1.8,2.5,3.3,5.5; Bits(#): 1; Output Drive (IOL/IOH)(Max)(mA): 8/-8; F @ Nom Voltage(Max)(Mhz): 50; Special Features: 1.8V to 3.3V Up Translation,3.3V to 1.8V Down Translation,5V Input Tolerant; Input Type: TTL; Technology Family: LV1T; VCC(Min)(V): 1.6; AEC Category: Q200; AEC Qualified: N; CompType: IC; SizeAreaWB_mm2: 9.3; SizeArea_mm2: 4.2; SizeX_mm: 2.1; SizeY_mm: 2.0; SizeZ_mm: 1.1
U8 = CMP-0078516-1: Remote and Local Temperature Sensor with N-Factor and Series-R Correction in MSOP-8, D0008A (SOIC-8); Alternate Manufacturer: Texas Instruments; SizeAreaWB_mm2: 56.58; SizeZ_mm: 1.75; SizeX_mm: 4.9; SizeY_mm: 6.2; SizeArea_mm2: 30.38; CompType: IC; AEC Qualified: N; AEC Category: Q200
U9 U10 = CMP-0098432-1: Current Sense Amplifier 1 Circuit 10-VSSOP; Manufacturer: Texas Instruments; SizeZ_mm: 1.1mm; AEC Qualified: No; Input Bias Current: 0.01uA; Input Offset Voltage: 1mV; Max Supply Voltage: 5.5V; Min Supply Voltage: 2.7V; Nominal Supply Current: 640uA; Number Of Channels: 1; Standoff Height: 0.05mm; TaMax_C: +125°C; TaMin_C: -40°C; TJmax_C: +150°C
Y1 = CMP-0122114-1: 25 MHz XO (Standard) CMOS Oscillator 3.3V Standby (Power Down) 4-SMD, No Lead; Manufacturer: Wurth Electronics; Frequency Stability: 25ppm; Frequency_Fixed: 25MHz; SizeZ_mm: 1.2mm; Load Capacitance: 15pF; Max Supply Current: 12mA; Max Supply Voltage: 3.63V; Min Supply Voltage: 2.97V

## Sheet PROC195_RESET_CIRCUIT.SchDoc
size 431 x 279 mm; Date: Not shown in title block; ApprovedBy: Not shown in title block; CheckedBy: Not shown in title block; Author: Not shown in title block; CompanyName: Not shown in title block; Engineer: Not shown in title block; Organization: Not shown in title block; Address1: Not shown in title block; Address2: Not shown in title block; Address3: Not shown in title block; Address4: Not shown in title block; DocumentNumber: 1; Revision: Use project parameter SCH_Rev; SheetNumber: 16; SheetTotal: 20; PageSetup: Record=PageOptions¦CenterHorizontal=True¦CenterVertical=True¦PrintScale=1.00¦XCorrection=1.00¦YCorrection=1.00¦PrintKind=0¦BorderSize=5000000¦LeftOffset=0¦BottomOffset=0¦Orientation=2¦PaperLength=1000¦PaperWidth=1000¦Scale=100¦PaperSource=15¦PrintQuality=600¦MediaType=1¦DitherType=10¦PaperKind=Letter¦PrintScaleMode=1
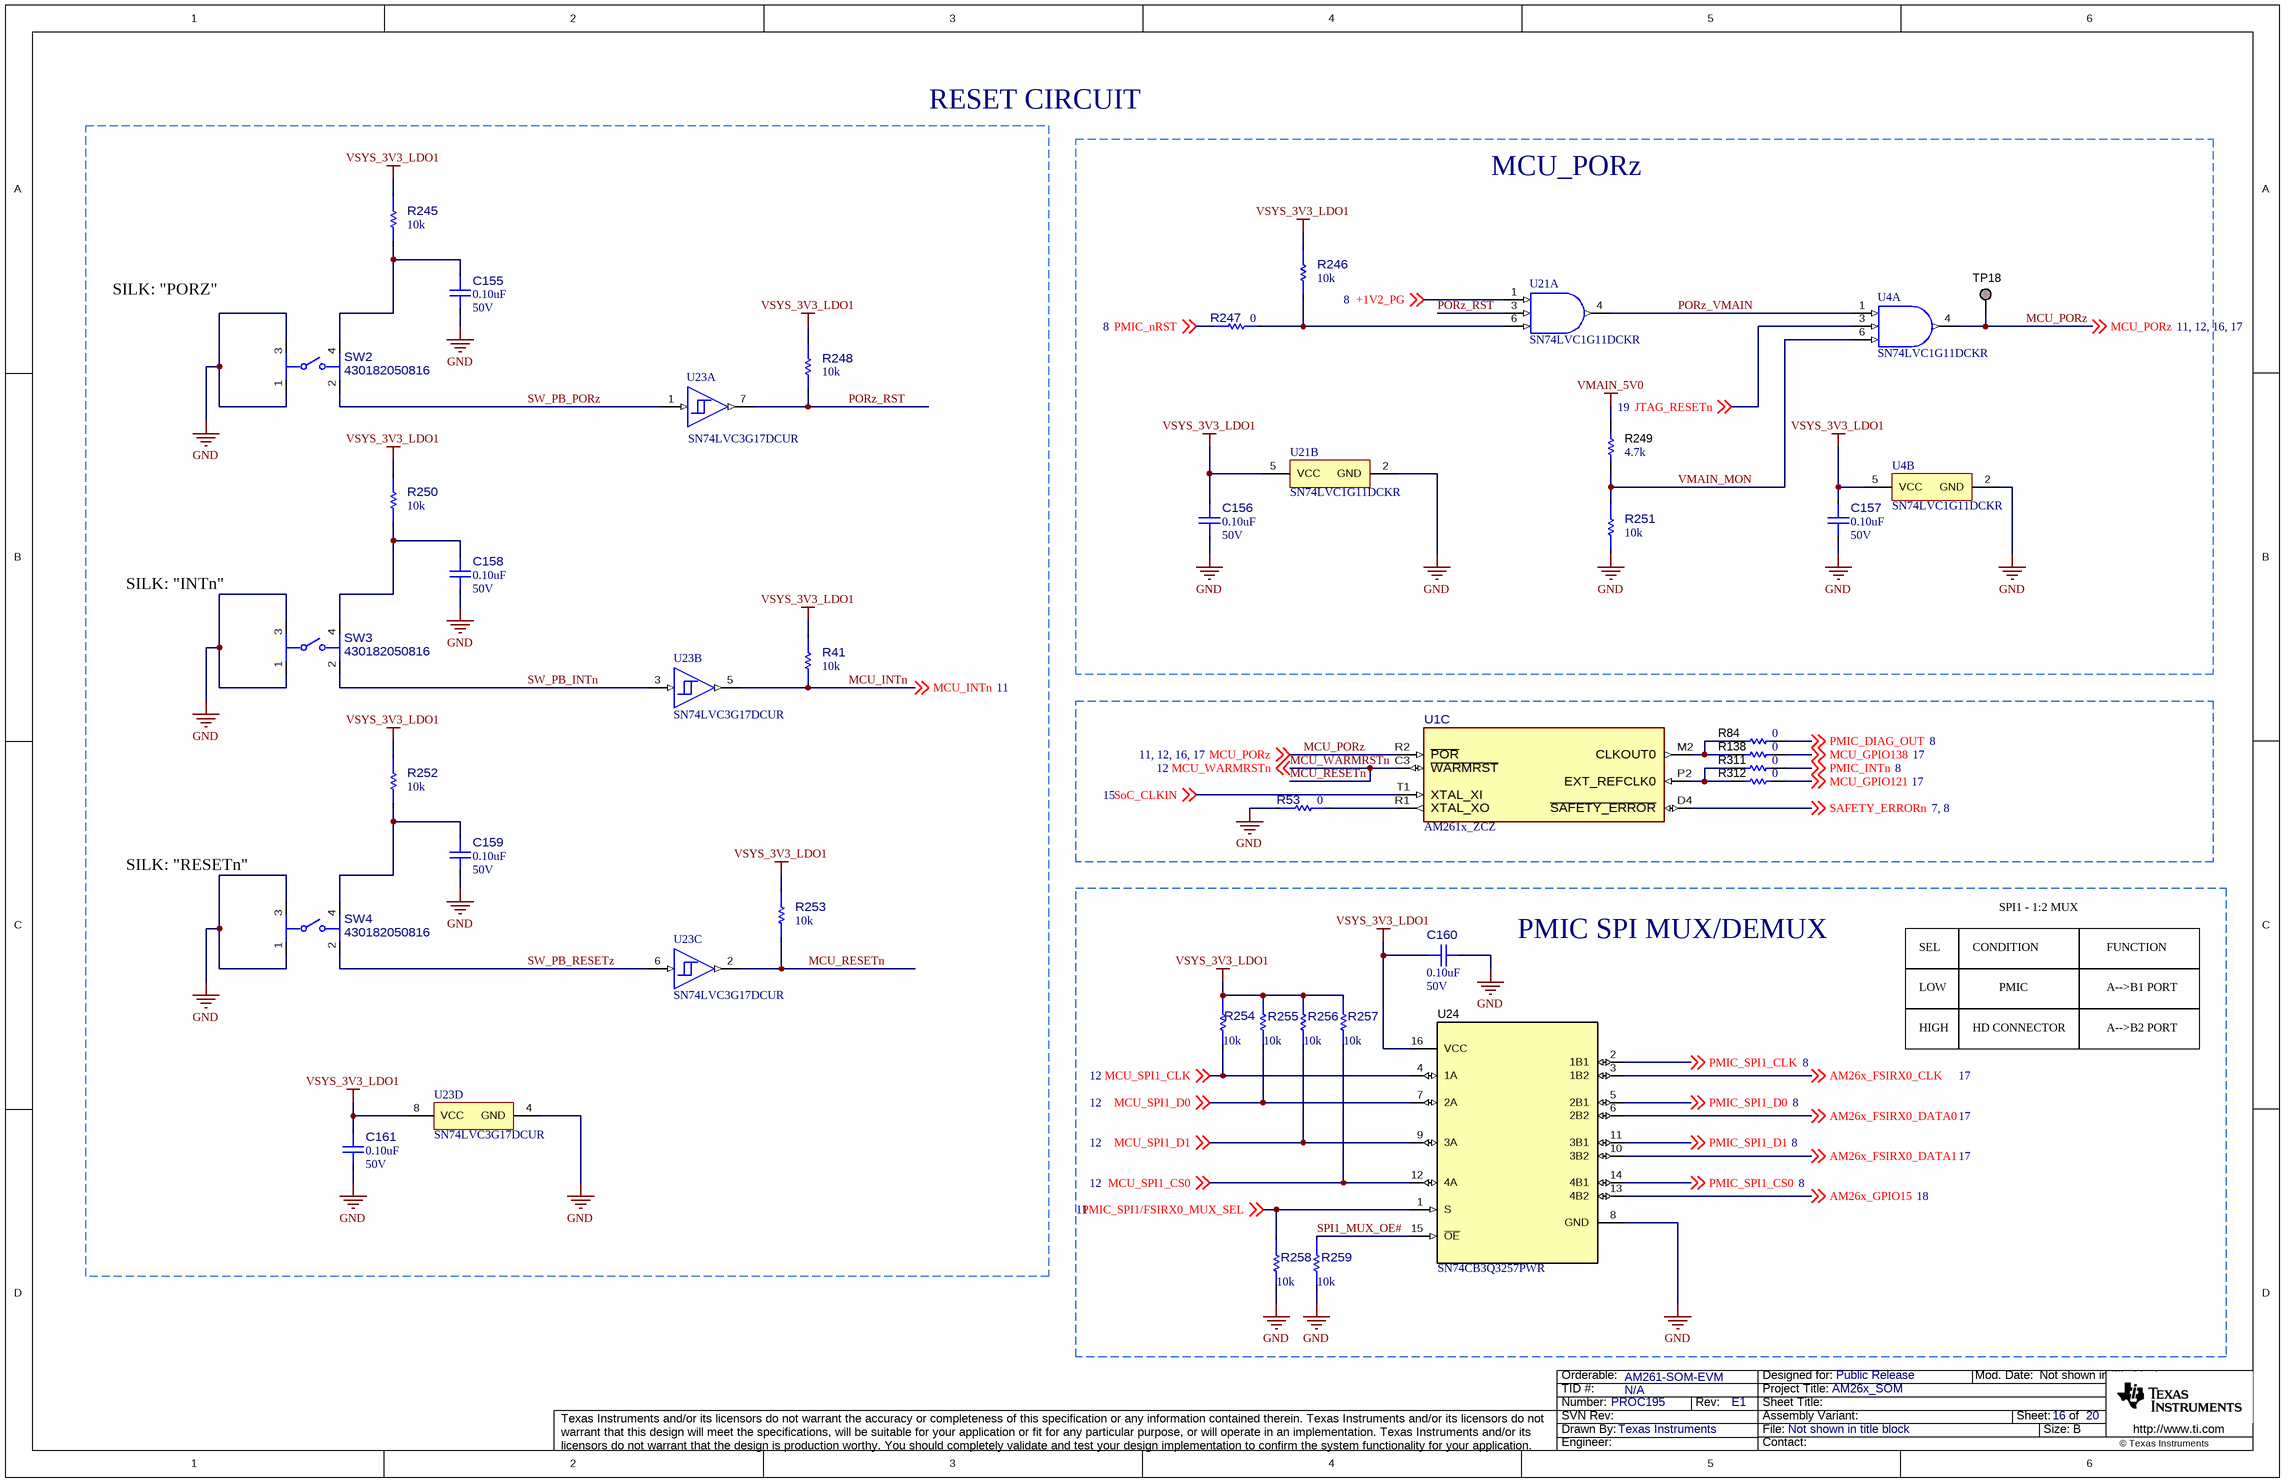
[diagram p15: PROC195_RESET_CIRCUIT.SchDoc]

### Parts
C155  ValueDisplayed: 0.10uF  VDC_V: 50V  [FP-GRM155R71H104KE14D_0402-MFG]  (hidden comment: GRM155R71H104KE14D)
C156  ValueDisplayed: 0.10uF  VDC_V: 50V  [FP-GRM155R71H104KE14D_0402-MFG]  (hidden comment: GRM155R71H104KE14D)
C157  ValueDisplayed: 0.10uF  VDC_V: 50V  [FP-GRM155R71H104KE14D_0402-MFG]  (hidden comment: GRM155R71H104KE14D)
C158  ValueDisplayed: 0.10uF  VDC_V: 50V  [FP-GRM155R71H104KE14D_0402-MFG]  (hidden comment: GRM155R71H104KE14D)
C159  ValueDisplayed: 0.10uF  VDC_V: 50V  [FP-GRM155R71H104KE14D_0402-MFG]  (hidden comment: GRM155R71H104KE14D)
C160  ValueDisplayed: 0.10uF  VDC_V: 50V  [FP-GRM155R71H104KE14D_0402-MFG]  (hidden comment: GRM155R71H104KE14D)
C161  ValueDisplayed: 0.10uF  VDC_V: 50V  [FP-GRM155R71H104KE14D_0402-MFG]  (hidden comment: GRM155R71H104KE14D)
R41  value 10k  [FP-RC0402JR-0710KL_0402-MFG]  (hidden comment: RC0402JR-0710KL)
R53  value 0  [FP-ERJ-2GE0R00X_0402-MFG]  (hidden comment: ERJ-2GE0R00X)
R84  ValueDisplayed: 0  [0201]  (hidden comment: ERJ-1GN0R00C)
R138  ValueDisplayed: 0  [0201]  (hidden comment: ERJ-1GN0R00C)
R245  value 10k  [FP-RC0402JR-0710KL_0402-MFG]  (hidden comment: RC0402JR-0710KL)
R246  value 10k  [FP-RC0402JR-0710KL_0402-MFG]  (hidden comment: RC0402JR-0710KL)
R247  value 0  [FP-ERJ-2GE0R00X_0402-MFG]  (hidden comment: ERJ-2GE0R00X)
R248  value 10k  [FP-RC0402JR-0710KL_0402-MFG]  (hidden comment: RC0402JR-0710KL)
R249  ValueDisplayed: 4.7k  [0402]  (hidden comment: CRCW04024K70JNED)
R250  value 10k  [FP-RC0402JR-0710KL_0402-MFG]  (hidden comment: RC0402JR-0710KL)
R251  value 10k  [FP-RC0402JR-0710KL_0402-MFG]  (hidden comment: RC0402JR-0710KL)
R252  value 10k  [FP-RC0402JR-0710KL_0402-MFG]  (hidden comment: RC0402JR-0710KL)
R253  value 10k  [FP-RC0402JR-0710KL_0402-MFG]  (hidden comment: RC0402JR-0710KL)
R254  value 10k  [FP-RC0402JR-0710KL_0402-MFG]  (hidden comment: RC0402JR-0710KL)
R255  value 10k  [FP-RC0402JR-0710KL_0402-MFG]  (hidden comment: RC0402JR-0710KL)
R256  value 10k  [FP-RC0402JR-0710KL_0402-MFG]  (hidden comment: RC0402JR-0710KL)
R257  value 10k  [FP-RC0402JR-0710KL_0402-MFG]  (hidden comment: RC0402JR-0710KL)
R258  value 10k  [FP-RC0402JR-0710KL_0402-MFG]  (hidden comment: RC0402JR-0710KL)
R259  value 10k  [FP-RC0402JR-0710KL_0402-MFG]  (hidden comment: RC0402JR-0710KL)
R311  ValueDisplayed: 0  [0201]  (hidden comment: ERJ-1GN0R00C)
R312  ValueDisplayed: 0  [0201]  (hidden comment: ERJ-1GN0R00C)
SW2  430182050816  [FP-430182050816_SMT_SW_6MM2_6MM2-MFG]
SW3  430182050816  [FP-430182050816_SMT_SW_6MM2_6MM2-MFG]
SW4  430182050816  [FP-430182050816_SMT_SW_6MM2_6MM2-MFG]
TP18  TESTPOINT  [TP_25MIL-SMT]  (value not drawn)  (no BOM)
U1  AM261x_ZCZ  [ZCZ0324A-MFG]  (part C of 13)
U4  SN74LVC1G11DCKR  [DCK0006A_N]  (parts A,B of 2)
U21  SN74LVC1G11DCKR  [DCK0006A_N]  (parts A,B of 2)
U23  SN74LVC3G17DCUR  [DCU0008A_N]  (parts A,B,C,D of 4)
U24  SN74CB3Q3257PWR  [PW0016A_L]

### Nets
GND: C155.2 C156.2 C157.2 C158.2 C159.2 C160.2 C161.2 R53.1 R251.2 R258.2 R259.2 SW2.1 SW2.3 SW3.1 SW3.3 SW4.1 SW4.3 U4.2(GND) U21.2(GND) U23.4(GND) U24.8(GND)
VMAIN_5V0: R249.1
VSYS_3V3_LDO1: C156.1 C157.1 C160.1 C161.1 R41.1 R245.1 R246.1 R248.1 R250.1 R252.1 R253.1 R254.1 R255.1 R256.1 R257.1 U4.5(VCC) U21.5(VCC) U23.8(VCC) U24.16(VCC)
+1V2_PG: U21.1(A) ; off-sheet +1V2_PG
AM26x_FSIRX0_CLK: U24.3(1B2) ; off-sheet AM26x_FSIRX0_CLK
AM26x_FSIRX0_DATA0: U24.6(2B2) ; off-sheet AM26x_FSIRX0_DATA0
AM26x_FSIRX0_DATA1: U24.10(3B2) ; off-sheet AM26x_FSIRX0_DATA1
AM26x_GPIO15: U24.13(4B2) ; off-sheet AM26x_GPIO15
JTAG_RESETn: U4.3(B) ; off-sheet JTAG_RESETn
MCU_GPIO121: R312.2 ; off-sheet MCU_GPIO121
MCU_GPIO138: R138.2 ; off-sheet MCU_GPIO138
MCU_INTn: R41.2 U23.5(2Y) ; off-sheet MCU_INTn
MCU_PORz: TP18.1 U1.R2(~{POR}) U4.4(Y) ; off-sheet MCU_PORz
MCU_RESETn: R253.2 U1.C3(~{WARMRST}) U23.2(3Y) ; off-sheet MCU_WARMRSTn  [also labelled MCU_WARMRSTn]
MCU_SPI1_CLK: R254.2 U24.4(1A) ; off-sheet MCU_SPI1_CLK
MCU_SPI1_CS0: R257.2 U24.12(4A) ; off-sheet MCU_SPI1_CS0
MCU_SPI1_D0: R255.2 U24.7(2A) ; off-sheet MCU_SPI1_D0
MCU_SPI1_D1: R256.2 U24.9(3A) ; off-sheet MCU_SPI1_D1
PMIC_DIAG_OUT: R84.2 ; off-sheet PMIC_DIAG_OUT
PMIC_INTn: R311.2 ; off-sheet PMIC_INTn
PMIC_nRST: R247.1 ; off-sheet PMIC_nRST
PMIC_SPI1/FSIRX0_MUX_SEL: R258.1 U24.1(S) ; off-sheet PMIC_SPI1/FSIRX0_MUX_SEL
PMIC_SPI1_CLK: U24.2(1B1) ; off-sheet PMIC_SPI1_CLK
PMIC_SPI1_CS0: U24.14(4B1) ; off-sheet PMIC_SPI1_CS0
PMIC_SPI1_D0: U24.5(2B1) ; off-sheet PMIC_SPI1_D0
PMIC_SPI1_D1: U24.11(3B1) ; off-sheet PMIC_SPI1_D1
PORz_RST: R248.2 U21.3(B) U23.7(1Y)
PORz_VMAIN: U4.1(A) U21.4(Y)
SAFETY_ERRORn: U1.D4(~{SAFETY_ERROR}) ; off-sheet SAFETY_ERRORn
SoC_CLKIN: U1.T1(XTAL_XI) ; off-sheet SoC_CLKIN
SPI1_MUX_OE#: R259.1 U24.15(~{OE})
SW_PB_INTn: SW3.2 U23.3(2A)
SW_PB_PORz: SW2.2 U23.1(1A)
SW_PB_RESETz: SW4.2 U23.6(3A)
VMAIN_MON: R249.2 R251.1 U4.6(C)
NetC155_1: C155.1 R245.2 SW2.4
NetC158_1: C158.1 R250.2 SW3.4
NetC159_1: C159.1 R252.2 SW4.4
NetR53_2: R53.2 U1.R1(XTAL_XO)
NetR84_1: R84.1 R138.1 U1.M2(CLKOUT0)
NetR246_2: R246.2 R247.2 U21.6(C)
NetR311_1: R311.1 R312.1 U1.P2(EXT_REFCLK0)

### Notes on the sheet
- RESET CIRCUIT
- MCU_PORz
- SILK: "PORZ"
- SILK: "INTn"
- SILK: "RESETn"
- PMIC SPI MUX/DEMUX
- SEL
- CONDITION
- SPI1 - 1:2 MUX
- FUNCTION
- LOW
- HIGH
- HD CONNECTOR
- PMIC
- A-->B1 PORT
- A-->B2 PORT

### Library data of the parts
C155-C161 = CMP-0096855-1: as C105 on sheet PROC195_DAC
R41 R245 R246 R248 R250-R259 = CMP-0094798-1: as R298-R303 on sheet PROC195_DAC
R53 R247 = CMP-0002710-1: as R235 on sheet PROC195_DAC
R84 R138 R311 R312 = CMP-0065361-1: as R6 on sheet PROC195_DAC
R249 = CMP-0026938-5: RES, 4.7 k, 5%, 0.063 W, AEC-Q200 Grade 0, 0402; Manufacturer: Vishay-Dale; AEC Grade: 0; AEC Qualified: Y; Power_W: 63mW; SizeZ_mm: 0.6; TempCo: 200 ppm/C; VDC_V: 50V; Value: 4.7k; Value_Code: 4k70; EIA_Code: E24; SizeX_mm: 1; SizeY_mm: 0.5; Value2: 0.063W; AEC Category: Q200
SW2-SW4 = CMP-0097324-1: Switch Tactile N.O. SPST Round Button Gull Wing 0.05A 12VDC 1000000Cycles 1.57N SMD Reel; Manufacturer: Wurth Electronics; AEC Qualified: No; Operating Force: 160gf; Coil Resistance_ohm: 100mΩ; VDC_V: 12V; Circuit: SPST-NO; SizeZ_mm: 5.15mm; Contact Current Rating: 50mA
TP18 = CMP-0078143-3: TEST POINT.  No entry in BOM.
U1 = CMP-0121930-1: as U1 on sheet PROC195_DAC
U4 U21 = CMP-0051216-3: Single 3-Input Positive-AND Gate, DCK0006A (SOT-SC70-6); Manufacturer: Texas Instruments; Output Type: CMOS; Bits(#): 1; Input Type: CMOS/TTL; Technology Family: LVC; Schmitt Trigger: No; VCC(Max)(V): 5.5; Gate Type: AND; Rating: Catalog; Output Drive (IOL/IOH)(Max)(mA): 32/-32; ICC @ Nom Voltage(Max)(mA): 0.01; VCC(Min)(V): 1.65; F @ Nom Voltage(Max)(Mhz): 150; Logic: True; Voltage(Nom)(V): 1.8,2.5,3.3,5; tpd @ Nom Voltage(Max)(ns): 20,7.8,6.2,4.6; AEC Category: Q200; AEC Qualified: N; CompType: IC; SizeAreaWB_mm2: 9.3; SizeArea_mm2: 4.2; SizeX_mm: 2.1; SizeY_mm: 2.0; SizeZ_mm: 1.1
U23 = CMP-0051981-2: TRIPLE SCHMITT-TRIGGER BUFFER, DCU0008A (VSSOP-8); Manufacturer: Texas Instruments; Voltage(Nom)(V): 1.8,2.5,3.3,5; VCC(Max)(V): 5.5; Output Drive (IOL/IOH)(Max)(mA): 32/-32; Output Type: CMOS; tpd @ Nom Voltage(Max)(ns): 9.2,6.2,5.4,4.1; Rating: Catalog; Input Type: CMOS/TTL; 3-State Output: No; Bits(#): 3; Schmitt Trigger: Yes; Logic: True; Technology Family: LVC; F @ Nom Voltage(Max)(Mhz): 150; ICC @ Nom Voltage(Max)(mA): 0.01; VCC(Min)(V): 1.65; AEC Category: Q200; AEC Qualified: N; CompType: IC; SizeAreaWB_mm2: 12.6; SizeArea_mm2: 6.4; SizeX_mm: 3.2; SizeY_mm: 2.0; SizeZ_mm: 0.9
U24 = CMP-0076540-1: as U13 on sheet PROC195_DAC

## Sheet PROC195_High_density_conn_1_2.SchDoc
size 431 x 279 mm; DocumentNumber: 10; SheetNumber: 17; SheetTotal: 20; PageSetup: Record=PageOptions¦CenterHorizontal=True¦CenterVertical=True¦PrintScale=1.00¦XCorrection=1.00¦YCorrection=1.00¦PrintKind=0¦BorderSize=5000000¦LeftOffset=0¦BottomOffset=0¦Orientation=2¦PaperLength=1000¦PaperWidth=1000¦Scale=100¦PaperSource=15¦PrintQuality=600¦MediaType=1¦DitherType=10¦PaperKind=Letter¦PrintScaleMode=1
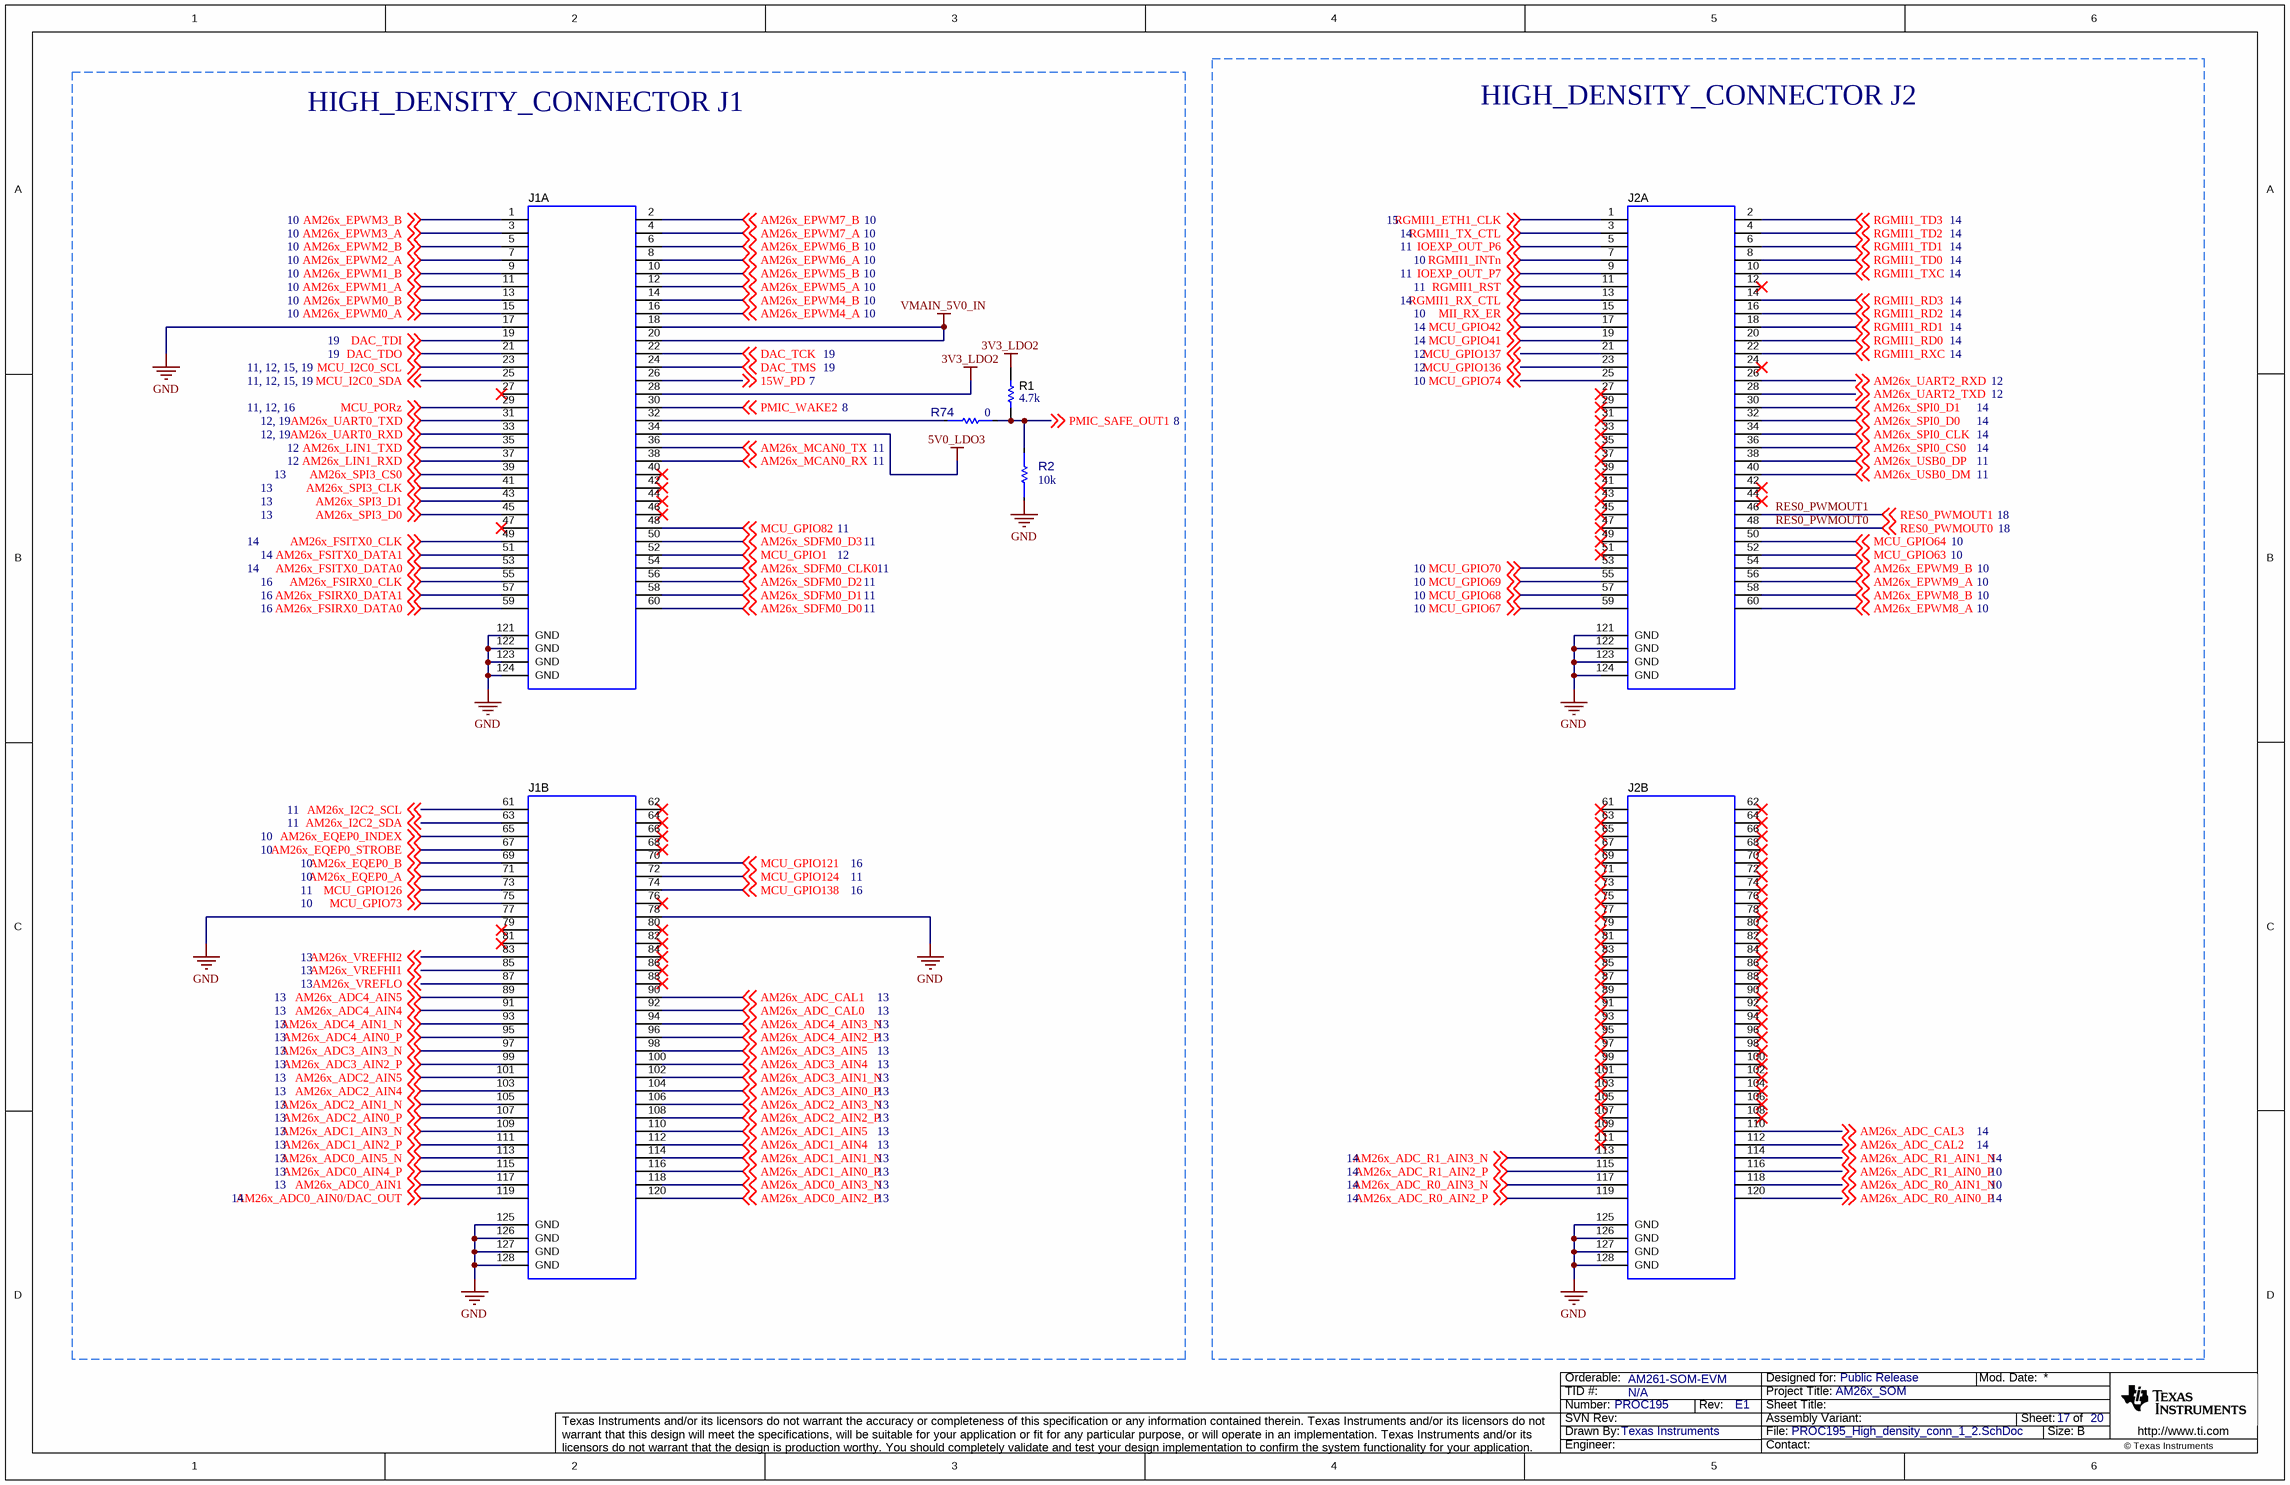
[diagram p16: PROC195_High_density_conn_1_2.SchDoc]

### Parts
J1  QSH-060-01-L-D-A  [CONN_QSH-060-01-L-D-A]  (value not drawn)  (parts A,B of 2)
J2  QSH-060-01-L-D-A  [CONN_QSH-060-01-L-D-A]  (value not drawn)  (parts A,B of 2)
R1  value 4.7k  [0402]  (hidden comment: CRCW04024K70JNED)
R2  value 10k  [FP-RC0402JR-0710KL_0402-MFG]  (hidden comment: RC0402JR-0710KL)
R74  Res_ohm: 0  [FP-ERJ-2GE0R00X_0402-MFG]  (hidden comment: ERJ-2GE0R00X)

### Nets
3V3_LDO2: J1.28 R1.2
5V0_LDO3: J1.34
GND: J1.17 J1.77 J1.78 J1.121(GND) J1.122(GND) J1.123(GND) J1.124(GND) J1.125(GND) J1.126(GND) J1.127(GND) J1.128(GND) J2.121(GND) J2.122(GND) J2.123(GND) J2.124(GND) J2.125(GND) J2.126(GND) J2.127(GND) J2.128(GND) R2.1
VMAIN_5V0_IN: J1.18 J1.20
15W_PD: J1.26 ; off-sheet 15W_PD
AM26x_ADC0_AIN0/DAC_OUT: J1.119 ; off-sheet AM26x_ADC0_AIN0/DAC_OUT
AM26x_ADC0_AIN1: J1.117 ; off-sheet AM26x_ADC0_AIN1
AM26x_ADC0_AIN2_P: J1.120 ; off-sheet AM26x_ADC0_AIN2_P
AM26x_ADC0_AIN3_N: J1.118 ; off-sheet AM26x_ADC0_AIN3_N
AM26x_ADC0_AIN4_P: J1.115 ; off-sheet AM26x_ADC0_AIN4_P
AM26x_ADC0_AIN5_N: J1.113 ; off-sheet AM26x_ADC0_AIN5_N
AM26x_ADC1_AIN0_P: J1.116 ; off-sheet AM26x_ADC1_AIN0_P
AM26x_ADC1_AIN1_N: J1.114 ; off-sheet AM26x_ADC1_AIN1_N
AM26x_ADC1_AIN2_P: J1.111 ; off-sheet AM26x_ADC1_AIN2_P
AM26x_ADC1_AIN3_N: J1.109 ; off-sheet AM26x_ADC1_AIN3_N
AM26x_ADC1_AIN4: J1.112 ; off-sheet AM26x_ADC1_AIN4
AM26x_ADC1_AIN5: J1.110 ; off-sheet AM26x_ADC1_AIN5
AM26x_ADC2_AIN0_P: J1.107 ; off-sheet AM26x_ADC2_AIN0_P
AM26x_ADC2_AIN1_N: J1.105 ; off-sheet AM26x_ADC2_AIN1_N
AM26x_ADC2_AIN2_P: J1.108 ; off-sheet AM26x_ADC2_AIN2_P
AM26x_ADC2_AIN3_N: J1.106 ; off-sheet AM26x_ADC2_AIN3_N
AM26x_ADC2_AIN4: J1.103 ; off-sheet AM26x_ADC2_AIN4
AM26x_ADC2_AIN5: J1.101 ; off-sheet AM26x_ADC2_AIN5
AM26x_ADC3_AIN0_P: J1.104 ; off-sheet AM26x_ADC3_AIN0_P
AM26x_ADC3_AIN1_N: J1.102 ; off-sheet AM26x_ADC3_AIN1_N
AM26x_ADC3_AIN2_P: J1.99 ; off-sheet AM26x_ADC3_AIN2_P
AM26x_ADC3_AIN3_N: J1.97 ; off-sheet AM26x_ADC3_AIN3_N
AM26x_ADC3_AIN4: J1.100 ; off-sheet AM26x_ADC3_AIN4
AM26x_ADC3_AIN5: J1.98 ; off-sheet AM26x_ADC3_AIN5
AM26x_ADC4_AIN0_P: J1.95 ; off-sheet AM26x_ADC4_AIN0_P
AM26x_ADC4_AIN1_N: J1.93 ; off-sheet AM26x_ADC4_AIN1_N
AM26x_ADC4_AIN2_P: J1.96 ; off-sheet AM26x_ADC4_AIN2_P
AM26x_ADC4_AIN3_N: J1.94 ; off-sheet AM26x_ADC4_AIN3_N
AM26x_ADC4_AIN4: J1.91 ; off-sheet AM26x_ADC4_AIN4
AM26x_ADC4_AIN5: J1.89 ; off-sheet AM26x_ADC4_AIN5
AM26x_ADC_CAL0: J1.92 ; off-sheet AM26x_ADC_CAL0
AM26x_ADC_CAL1: J1.90 ; off-sheet AM26x_ADC_CAL1
AM26x_ADC_CAL2: J2.112 ; off-sheet AM26x_ADC_CAL2
AM26x_ADC_CAL3: J2.110 ; off-sheet AM26x_ADC_CAL3
AM26x_ADC_R0_AIN0_P: J2.120 ; off-sheet AM26x_ADC_R0_AIN0_P
AM26x_ADC_R0_AIN1_N: J2.118 ; off-sheet AM26x_ADC_R0_AIN1_N
AM26x_ADC_R0_AIN2_P: J2.119 ; off-sheet AM26x_ADC_R0_AIN2_P
AM26x_ADC_R0_AIN3_N: J2.117 ; off-sheet AM26x_ADC_R0_AIN3_N
AM26x_ADC_R1_AIN0_P: J2.116 ; off-sheet AM26x_ADC_R1_AIN0_P
AM26x_ADC_R1_AIN1_N: J2.114 ; off-sheet AM26x_ADC_R1_AIN1_N
AM26x_ADC_R1_AIN2_P: J2.115 ; off-sheet AM26x_ADC_R1_AIN2_P
AM26x_ADC_R1_AIN3_N: J2.113 ; off-sheet AM26x_ADC_R1_AIN3_N
AM26x_EPWM0_A: J1.15 ; off-sheet AM26x_EPWM0_A
AM26x_EPWM0_B: J1.13 ; off-sheet AM26x_EPWM0_B
AM26x_EPWM1_A: J1.11 ; off-sheet AM26x_EPWM1_A
AM26x_EPWM1_B: J1.9 ; off-sheet AM26x_EPWM1_B
AM26x_EPWM2_A: J1.7 ; off-sheet AM26x_EPWM2_A
AM26x_EPWM2_B: J1.5 ; off-sheet AM26x_EPWM2_B
AM26x_EPWM3_A: J1.3 ; off-sheet AM26x_EPWM3_A
AM26x_EPWM3_B: J1.1 ; off-sheet AM26x_EPWM3_B
AM26x_EPWM4_A: J1.16 ; off-sheet AM26x_EPWM4_A
AM26x_EPWM4_B: J1.14 ; off-sheet AM26x_EPWM4_B
AM26x_EPWM5_A: J1.12 ; off-sheet AM26x_EPWM5_A
AM26x_EPWM5_B: J1.10 ; off-sheet AM26x_EPWM5_B
AM26x_EPWM6_A: J1.8 ; off-sheet AM26x_EPWM6_A
AM26x_EPWM6_B: J1.6 ; off-sheet AM26x_EPWM6_B
AM26x_EPWM7_A: J1.4 ; off-sheet AM26x_EPWM7_A
AM26x_EPWM7_B: J1.2 ; off-sheet AM26x_EPWM7_B
AM26x_EPWM8_A: J2.60 ; off-sheet AM26x_EPWM8_A
AM26x_EPWM8_B: J2.58 ; off-sheet AM26x_EPWM8_B
AM26x_EPWM9_A: J2.56 ; off-sheet AM26x_EPWM9_A
AM26x_EPWM9_B: J2.54 ; off-sheet AM26x_EPWM9_B
AM26x_EQEP0_A: J1.71 ; off-sheet AM26x_EQEP0_A
AM26x_EQEP0_B: J1.69 ; off-sheet AM26x_EQEP0_B
AM26x_EQEP0_INDEX: J1.65 ; off-sheet AM26x_EQEP0_INDEX
AM26x_EQEP0_STROBE: J1.67 ; off-sheet AM26x_EQEP0_STROBE
AM26x_FSIRX0_CLK: J1.55 ; off-sheet AM26x_FSIRX0_CLK
AM26x_FSIRX0_DATA0: J1.59 ; off-sheet AM26x_FSIRX0_DATA0
AM26x_FSIRX0_DATA1: J1.57 ; off-sheet AM26x_FSIRX0_DATA1
AM26x_FSITX0_CLK: J1.49 ; off-sheet AM26x_FSITX0_CLK
AM26x_FSITX0_DATA0: J1.53 ; off-sheet AM26x_FSITX0_DATA0
AM26x_FSITX0_DATA1: J1.51 ; off-sheet AM26x_FSITX0_DATA1
AM26x_I2C2_SCL: J1.61 ; off-sheet AM26x_I2C2_SCL
AM26x_I2C2_SDA: J1.63 ; off-sheet AM26x_I2C2_SDA
AM26x_LIN1_RXD: J1.37 ; off-sheet AM26x_LIN1_RXD
AM26x_LIN1_TXD: J1.35 ; off-sheet AM26x_LIN1_TXD
AM26x_MCAN0_RX: J1.38 ; off-sheet AM26x_MCAN0_RX
AM26x_MCAN0_TX: J1.36 ; off-sheet AM26x_MCAN0_TX
AM26x_SDFM0_CLK0: J1.54 ; off-sheet AM26x_SDFM0_CLK0
AM26x_SDFM0_D0: J1.60 ; off-sheet AM26x_SDFM0_D0
AM26x_SDFM0_D1: J1.58 ; off-sheet AM26x_SDFM0_D1
AM26x_SDFM0_D2: J1.56 ; off-sheet AM26x_SDFM0_D2
AM26x_SDFM0_D3: J1.50 ; off-sheet AM26x_SDFM0_D3
AM26x_SPI0_CLK: J2.34 ; off-sheet AM26x_SPI0_CLK
AM26x_SPI0_CS0: J2.36 ; off-sheet AM26x_SPI0_CS0
AM26x_SPI0_D0: J2.32 ; off-sheet AM26x_SPI0_D0
AM26x_SPI0_D1: J2.30 ; off-sheet AM26x_SPI0_D1
AM26x_SPI3_CLK: J1.41 ; off-sheet AM26x_SPI3_CLK
AM26x_SPI3_CS0: J1.39 ; off-sheet AM26x_SPI3_CS0
AM26x_SPI3_D0: J1.45 ; off-sheet AM26x_SPI3_D0
AM26x_SPI3_D1: J1.43 ; off-sheet AM26x_SPI3_D1
AM26x_UART0_RXD: J1.33 ; off-sheet AM26x_UART0_RXD
AM26x_UART0_TXD: J1.31 ; off-sheet AM26x_UART0_TXD
AM26x_UART2_RXD: J2.26 ; off-sheet AM26x_UART2_RXD
AM26x_UART2_TXD: J2.28 ; off-sheet AM26x_UART2_TXD
AM26x_USB0_DM: J2.40 ; off-sheet AM26x_USB0_DM
AM26x_USB0_DP: J2.38 ; off-sheet AM26x_USB0_DP
AM26x_VREFHI1: J1.85 ; off-sheet AM26x_VREFHI1
AM26x_VREFHI2: J1.83 ; off-sheet AM26x_VREFHI2
AM26x_VREFLO: J1.87 ; off-sheet AM26x_VREFLO
DAC_TCK: J1.22 ; off-sheet DAC_TCK
DAC_TDI: J1.19 ; off-sheet DAC_TDI
DAC_TDO: J1.21 ; off-sheet DAC_TDO
DAC_TMS: J1.24 ; off-sheet DAC_TMS
IOEXP_OUT_P6: J2.5 ; off-sheet IOEXP_OUT_P6
IOEXP_OUT_P7: J2.9 ; off-sheet IOEXP_OUT_P7
MCU_GPIO1: J1.52 ; off-sheet MCU_GPIO1
MCU_GPIO41: J2.19 ; off-sheet MCU_GPIO41
MCU_GPIO42: J2.17 ; off-sheet MCU_GPIO42
MCU_GPIO63: J2.52 ; off-sheet MCU_GPIO63
MCU_GPIO64: J2.50 ; off-sheet MCU_GPIO64
MCU_GPIO67: J2.59 ; off-sheet MCU_GPIO67
MCU_GPIO68: J2.57 ; off-sheet MCU_GPIO68
MCU_GPIO69: J2.55 ; off-sheet MCU_GPIO69
MCU_GPIO70: J2.53 ; off-sheet MCU_GPIO70
MCU_GPIO73: J1.75 ; off-sheet MCU_GPIO73
MCU_GPIO74: J2.25 ; off-sheet MCU_GPIO74
MCU_GPIO82: J1.48 ; off-sheet MCU_GPIO82
MCU_GPIO121: J1.70 ; off-sheet MCU_GPIO121
MCU_GPIO124: J1.72 ; off-sheet MCU_GPIO124
MCU_GPIO126: J1.73 ; off-sheet MCU_GPIO126
MCU_GPIO136: J2.23 ; off-sheet MCU_GPIO136
MCU_GPIO137: J2.21 ; off-sheet MCU_GPIO137
MCU_GPIO138: J1.74 ; off-sheet MCU_GPIO138
MCU_I2C0_SCL: J1.23 ; off-sheet MCU_I2C0_SCL
MCU_I2C0_SDA: J1.25 ; off-sheet MCU_I2C0_SDA
MCU_PORz: J1.29 ; off-sheet MCU_PORz
MII_RX_ER: J2.15 ; off-sheet MII_RX_ER
PMIC_SAFE_OUT1: R1.1 R2.2 R74.2 ; off-sheet PMIC_SAFE_OUT1
PMIC_WAKE2: J1.30 ; off-sheet PMIC_WAKE2
RES0_PWMOUT0: J2.48 ; off-sheet RES0_PWMOUT0
RES0_PWMOUT1: J2.46 ; off-sheet RES0_PWMOUT1
RGMII1_ETH1_CLK: J2.1 ; off-sheet RGMII1_ETH1_CLK
RGMII1_INTn: J2.7 ; off-sheet RGMII1_INTn
RGMII1_RD0: J2.20 ; off-sheet RGMII1_RD0
RGMII1_RD1: J2.18 ; off-sheet RGMII1_RD1
RGMII1_RD2: J2.16 ; off-sheet RGMII1_RD2
RGMII1_RD3: J2.14 ; off-sheet RGMII1_RD3
RGMII1_RST: J2.11 ; off-sheet RGMII1_RST
RGMII1_RX_CTL: J2.13 ; off-sheet RGMII1_RX_CTL
RGMII1_RXC: J2.22 ; off-sheet RGMII1_RXC
RGMII1_TD0: J2.8 ; off-sheet RGMII1_TD0
RGMII1_TD1: J2.6 ; off-sheet RGMII1_TD1
RGMII1_TD2: J2.4 ; off-sheet RGMII1_TD2
RGMII1_TD3: J2.2 ; off-sheet RGMII1_TD3
RGMII1_TX_CTL: J2.3 ; off-sheet RGMII1_TX_CTL
RGMII1_TXC: J2.10 ; off-sheet RGMII1_TXC
NetJ1_32: J1.32 R74.1

Not connected (* = marked no-connect by the designer): J1 27* 40* 42* 44* 46* 47* 62* 64* 66* 68* 76* 79* 80* 81* 82* 84* 86* 88*; J2 12* 24* 27* 29* 31* 33* 35* 37* 39* 41* 42* 43* 44* 45* 47* 49* 51* 61* 62* 63* 64* 65* 66* 67* 68* 69* 70* 71* 72* 73* 74* 75* 76* 77* 78* 79* 80* 81* 82* 83* 84* 85* 86* 87* 88* 89* 90* 91* 92* 93* 94* 95* 96* 97* 98* 99* 100* 101* 102* 103* 104* 105* 106* 107* 108* 109* 111*

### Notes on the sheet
- HIGH_DENSITY_CONNECTOR J1
- HIGH_DENSITY_CONNECTOR J2

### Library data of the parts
J1 J2 = CMP-0055973-1: Connector,  0.5mm, 60x2, SMT; Manufacturer: Samtec; CT: FALSE
R1 = CMP-0026938-5: as R49 on sheet PROC195_CLK_LED_CURRENT_MON_TEMP_CONN
R2 = CMP-0094798-1: as R46 on sheet PROC195_CLK_LED_CURRENT_MON_TEMP_CONN
R74 = CMP-0002710-1: 0 Ohms Jumper Chip Resistor 0402 (1005 Metric) Automotive AEC-Q200 Thick Film; Manufacturer: Panasonic; Value: 0; SizeZ_mm: 0.4mm; AEC Qualified: Yes; AEC Grade: Grade 0; Power: 100mW

## Sheet PROC195_High_density_conn3_4.SchDoc
size 431 x 279 mm; DocumentNumber: 11; SheetNumber: 18; SheetTotal: 20; PageSetup: Record=PageOptions¦CenterHorizontal=True¦CenterVertical=True¦PrintScale=1.00¦XCorrection=1.00¦YCorrection=1.00¦PrintKind=0¦BorderSize=5000000¦LeftOffset=0¦BottomOffset=0¦Orientation=2¦PaperLength=1000¦PaperWidth=1000¦Scale=100¦PaperSource=15¦PrintQuality=600¦MediaType=1¦DitherType=10¦PaperKind=Letter¦PrintScaleMode=1
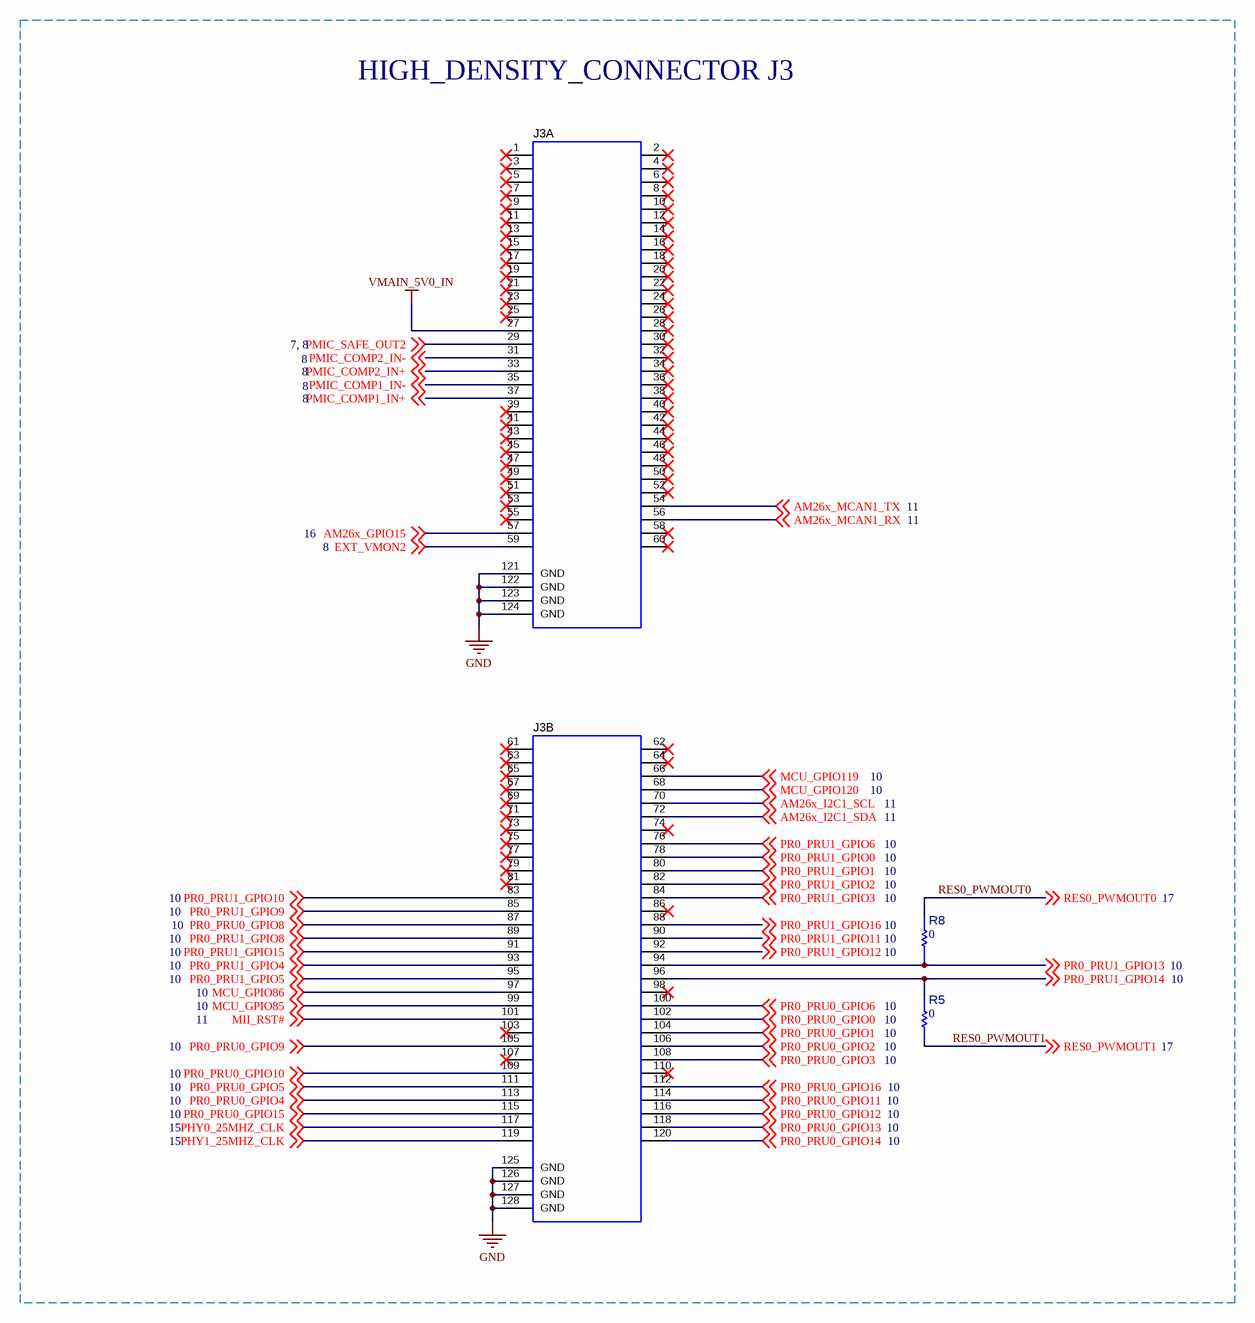
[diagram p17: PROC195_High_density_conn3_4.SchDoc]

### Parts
J3  QSH-060-01-L-D-A  [CONN_QSH-060-01-L-D-A]  (value not drawn)  (parts A,B of 2)
R5  value 0  [FP-ERJ-2GE0R00X_0402-MFG]  (hidden comment: ERJ-2GE0R00X)
R8  value 0  [FP-ERJ-2GE0R00X_0402-MFG]  (hidden comment: ERJ-2GE0R00X)

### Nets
GND: J3.121(GND) J3.122(GND) J3.123(GND) J3.124(GND) J3.125(GND) J3.126(GND) J3.127(GND) J3.128(GND)
VMAIN_5V0_IN: J3.27
AM26x_GPIO15: J3.57 ; off-sheet AM26x_GPIO15
AM26x_I2C1_SCL: J3.70 ; off-sheet AM26x_I2C1_SCL
AM26x_I2C1_SDA: J3.72 ; off-sheet AM26x_I2C1_SDA
AM26x_MCAN1_RX: J3.56 ; off-sheet AM26x_MCAN1_RX
AM26x_MCAN1_TX: J3.54 ; off-sheet AM26x_MCAN1_TX
EXT_VMON2: J3.59 ; off-sheet EXT_VMON2
MCU_GPIO85: J3.99 ; off-sheet MCU_GPIO85
MCU_GPIO86: J3.97 ; off-sheet MCU_GPIO86
MCU_GPIO119: J3.66 ; off-sheet MCU_GPIO119
MCU_GPIO120: J3.68 ; off-sheet MCU_GPIO120
MII_RST#: J3.101 ; off-sheet MII_RST#
PHY0_25MHZ_CLK: J3.117 ; off-sheet PHY0_25MHZ_CLK
PHY1_25MHZ_CLK: J3.119 ; off-sheet PHY1_25MHZ_CLK
PMIC_COMP1_IN+: J3.37 ; off-sheet PMIC_COMP1_IN+
PMIC_COMP1_IN-: J3.35 ; off-sheet PMIC_COMP1_IN-
PMIC_COMP2_IN+: J3.33 ; off-sheet PMIC_COMP2_IN+
PMIC_COMP2_IN-: J3.31 ; off-sheet PMIC_COMP2_IN-
PMIC_SAFE_OUT2: J3.29 ; off-sheet PMIC_SAFE_OUT2
PR0_PRU0_GPIO0: J3.102 ; off-sheet PR0_PRU0_GPIO0
PR0_PRU0_GPIO1: J3.104 ; off-sheet PR0_PRU0_GPIO1
PR0_PRU0_GPIO2: J3.106 ; off-sheet PR0_PRU0_GPIO2
PR0_PRU0_GPIO3: J3.108 ; off-sheet PR0_PRU0_GPIO3
PR0_PRU0_GPIO4: J3.113 ; off-sheet PR0_PRU0_GPIO4
PR0_PRU0_GPIO5: J3.111 ; off-sheet PR0_PRU0_GPIO5
PR0_PRU0_GPIO6: J3.100 ; off-sheet PR0_PRU0_GPIO6
PR0_PRU0_GPIO8: J3.87 ; off-sheet PR0_PRU0_GPIO8
PR0_PRU0_GPIO9: J3.105 ; off-sheet PR0_PRU0_GPIO9
PR0_PRU0_GPIO10: J3.109 ; off-sheet PR0_PRU0_GPIO10
PR0_PRU0_GPIO11: J3.114 ; off-sheet PR0_PRU0_GPIO11
PR0_PRU0_GPIO12: J3.116 ; off-sheet PR0_PRU0_GPIO12
PR0_PRU0_GPIO13: J3.118 ; off-sheet PR0_PRU0_GPIO13
PR0_PRU0_GPIO14: J3.120 ; off-sheet PR0_PRU0_GPIO14
PR0_PRU0_GPIO15: J3.115 ; off-sheet PR0_PRU0_GPIO15
PR0_PRU0_GPIO16: J3.112 ; off-sheet PR0_PRU0_GPIO16
PR0_PRU1_GPIO0: J3.78 ; off-sheet PR0_PRU1_GPIO0
PR0_PRU1_GPIO1: J3.80 ; off-sheet PR0_PRU1_GPIO1
PR0_PRU1_GPIO2: J3.82 ; off-sheet PR0_PRU1_GPIO2
PR0_PRU1_GPIO3: J3.84 ; off-sheet PR0_PRU1_GPIO3
PR0_PRU1_GPIO4: J3.93 ; off-sheet PR0_PRU1_GPIO4
PR0_PRU1_GPIO5: J3.95 ; off-sheet PR0_PRU1_GPIO5
PR0_PRU1_GPIO6: J3.76 ; off-sheet PR0_PRU1_GPIO6
PR0_PRU1_GPIO8: J3.89 ; off-sheet PR0_PRU1_GPIO8
PR0_PRU1_GPIO9: J3.85 ; off-sheet PR0_PRU1_GPIO9
PR0_PRU1_GPIO10: J3.83 ; off-sheet PR0_PRU1_GPIO10
PR0_PRU1_GPIO11: J3.90 ; off-sheet PR0_PRU1_GPIO11
PR0_PRU1_GPIO12: J3.92 ; off-sheet PR0_PRU1_GPIO12
PR0_PRU1_GPIO13: J3.94 R8.1 ; off-sheet PR0_PRU1_GPIO13
PR0_PRU1_GPIO14: J3.96 R5.1 ; off-sheet PR0_PRU1_GPIO14
PR0_PRU1_GPIO15: J3.91 ; off-sheet PR0_PRU1_GPIO15
PR0_PRU1_GPIO16: J3.88 ; off-sheet PR0_PRU1_GPIO16
RES0_PWMOUT0: R8.2 ; off-sheet RES0_PWMOUT0
RES0_PWMOUT1: R5.2 ; off-sheet RES0_PWMOUT1

Not connected (* = marked no-connect by the designer): J3 1* 2* 3* 4* 5* 6* 7* 8* 9* 10* 11* 12* 13* 14* 15* 16* 17* 18* 19* 20* 21* 22* 23* 24* 25* 26* 28* 30* 32* 34* 36* 38* 39* 40* 41* 42* 43* 44* 45* 46* 47* 48* 49* 50* 51* 52* 53* 55* 58* 60* 61* 62* 63* 64* 65* 67* 69* 71* 73* 74* 75* 77* 79* 81* 86* 98* 103* 107* 110*

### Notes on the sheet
- HIGH_DENSITY_CONNECTOR J3

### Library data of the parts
J3 = CMP-0055973-1: as J1 on sheet PROC195_High_density_conn_1_2
R5 R8 = CMP-0002710-1: as R3 on sheet PROC195_CLK_LED_CURRENT_MON_TEMP_CONN

## Sheet PROC195_MIPI_Emulation_conn.SchDoc
size 431 x 279 mm; SheetNumber: 19; SheetTotal: 20
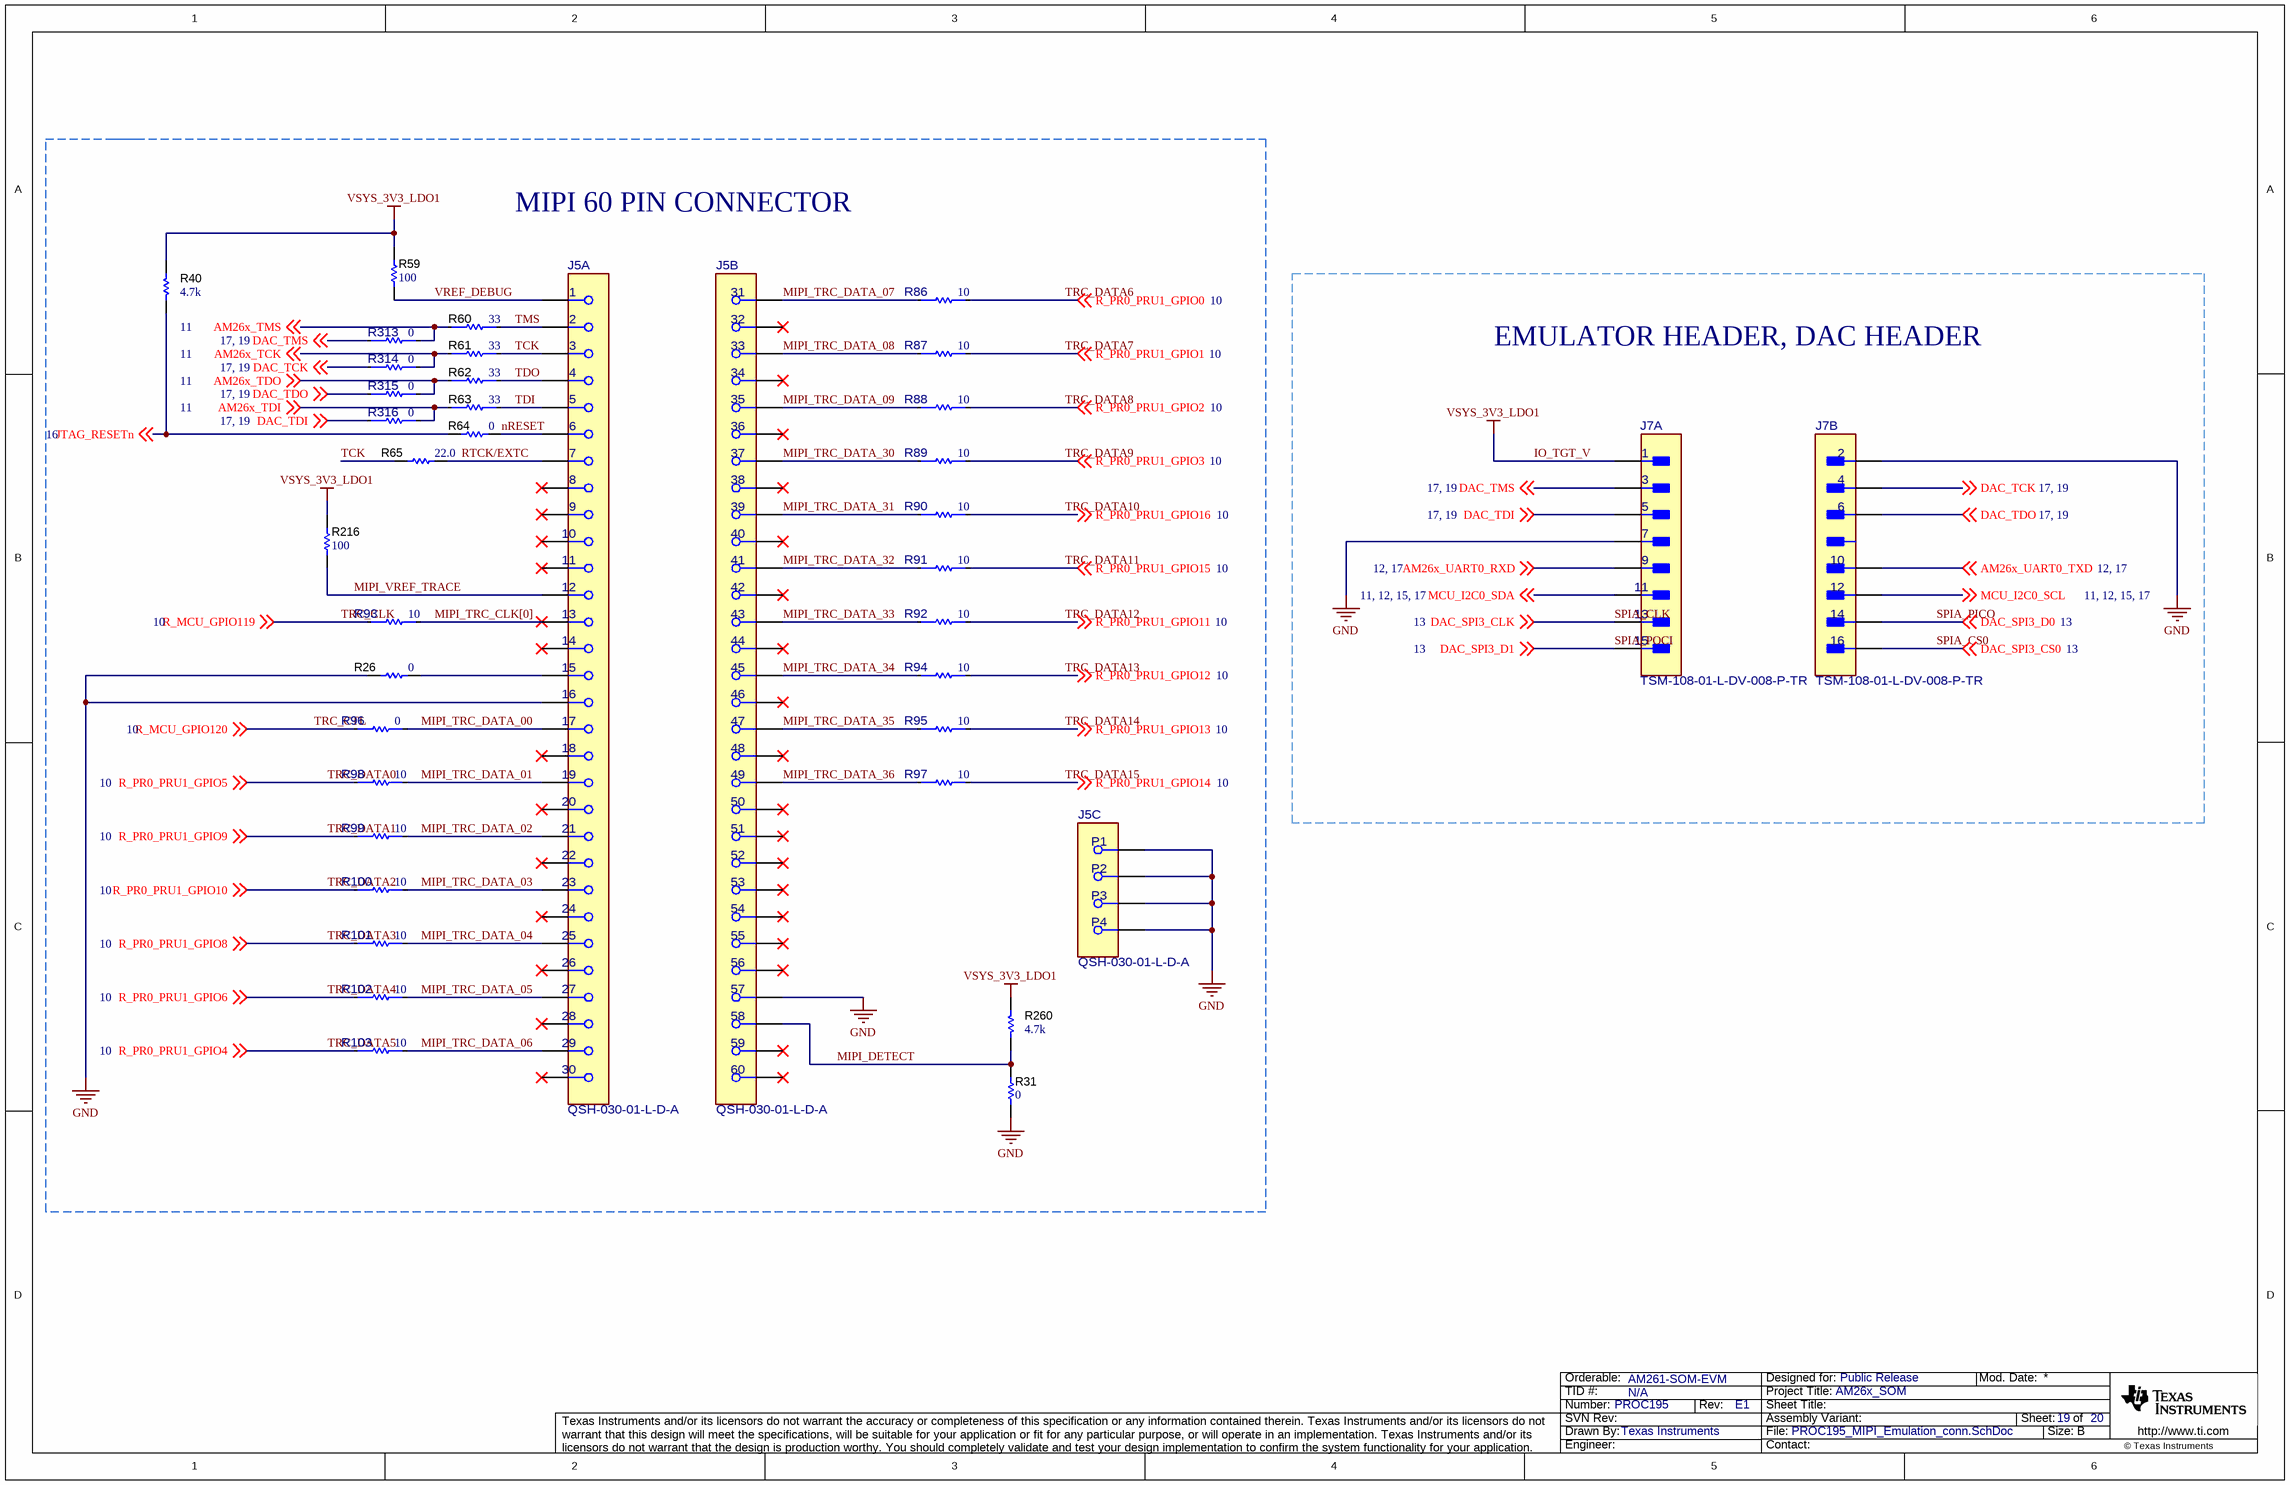
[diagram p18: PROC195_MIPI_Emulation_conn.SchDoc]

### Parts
J5  QSH-030-01-L-D-A  [FP-QSH-030-01-L-D-A_CONN_60-MFG]  (parts A,B,C of 3)
J7  TSM-108-01-L-DV-008-P-TR  [FP-TSM-108-01-L-DV-008-P-TR_HDR15-MFG]  (parts A,B of 2)
R26  ValueDisplayed: 0  [0201]  (hidden comment: ERJ-1GN0R00C)
R31  ValueDisplayed: 0  [0201]  (hidden comment: ERJ-1GN0R00C)
R40  value 4.7k  [0402]  (hidden comment: CRCW04024K70JNED)
R59  ValueDisplayed: 100  [0402]  (hidden comment: CRCW0402100RFKED)
R60  Res_ohm: 33  [FP-ERJ-2GEJ330X_0402-MFG]  (hidden comment: ERJ-2GEJ330X)
R61  Res_ohm: 33  [FP-ERJ-2GEJ330X_0402-MFG]  (hidden comment: ERJ-2GEJ330X)
R62  Res_ohm: 33  [FP-ERJ-2GEJ330X_0402-MFG]  (hidden comment: ERJ-2GEJ330X)
R63  Res_ohm: 33  [FP-ERJ-2GEJ330X_0402-MFG]  (hidden comment: ERJ-2GEJ330X)
R64  ValueDisplayed: 0  [0201]  (hidden comment: ERJ-1GN0R00C)
R65  ValueDisplayed: 22.0  [0201]  (hidden comment: RC0201FR-0722RL)
R86  value 10  [FP-RCC040210R0FKED_0402-MFG]  (hidden comment: RCC040210R0FKED)
R87  value 10  [FP-RCC040210R0FKED_0402-MFG]  (hidden comment: RCC040210R0FKED)
R88  value 10  [FP-RCC040210R0FKED_0402-MFG]  (hidden comment: RCC040210R0FKED)
R89  value 10  [FP-RCC040210R0FKED_0402-MFG]  (hidden comment: RCC040210R0FKED)
R90  value 10  [FP-RCC040210R0FKED_0402-MFG]  (hidden comment: RCC040210R0FKED)
R91  value 10  [FP-RCC040210R0FKED_0402-MFG]  (hidden comment: RCC040210R0FKED)
R92  value 10  [FP-RCC040210R0FKED_0402-MFG]  (hidden comment: RCC040210R0FKED)
R93  value 10  [FP-RCC040210R0FKED_0402-MFG]  (hidden comment: RCC040210R0FKED)
R94  value 10  [FP-RCC040210R0FKED_0402-MFG]  (hidden comment: RCC040210R0FKED)
R95  value 10  [FP-RCC040210R0FKED_0402-MFG]  (hidden comment: RCC040210R0FKED)
R96  value 0  [FP-ERJ-2GE0R00X_0402-MFG]  (hidden comment: ERJ-2GE0R00X)
R97  value 10  [FP-RCC040210R0FKED_0402-MFG]  (hidden comment: RCC040210R0FKED)
R98  value 10  [FP-RCC040210R0FKED_0402-MFG]  (hidden comment: RCC040210R0FKED)
R99  value 10  [FP-RCC040210R0FKED_0402-MFG]  (hidden comment: RCC040210R0FKED)
R100  value 10  [FP-RCC040210R0FKED_0402-MFG]  (hidden comment: RCC040210R0FKED)
R101  value 10  [FP-RCC040210R0FKED_0402-MFG]  (hidden comment: RCC040210R0FKED)
R102  value 10  [FP-RCC040210R0FKED_0402-MFG]  (hidden comment: RCC040210R0FKED)
R103  value 10  [FP-RCC040210R0FKED_0402-MFG]  (hidden comment: RCC040210R0FKED)
R216  ValueDisplayed: 100  [0402]  (hidden comment: CRCW0402100RFKED)
R260  value 4.7k  [0402]  (hidden comment: CRCW04024K70JNED)
R313  value 0  [FP-ERJ-2GE0R00X_0402-MFG]  (hidden comment: ERJ-2GE0R00X)
R314  value 0  [FP-ERJ-2GE0R00X_0402-MFG]  (hidden comment: ERJ-2GE0R00X)
R315  value 0  [FP-ERJ-2GE0R00X_0402-MFG]  (hidden comment: ERJ-2GE0R00X)
R316  value 0  [FP-ERJ-2GE0R00X_0402-MFG]  (hidden comment: ERJ-2GE0R00X)

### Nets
GND: J5.16 J5.57 J5.P1 J5.P2 J5.P3 J5.P4 J7.2 J7.7 R26.1 R31.1
VSYS_3V3_LDO1: J7.1 R40.2 R59.2 R216.1 R260.2
AM26x_TCK: R61.1 R314.2 ; off-sheet AM26x_TCK
AM26x_TDI: R63.1 R316.2 ; off-sheet AM26x_TDI
AM26x_TDO: R62.1 R315.2 ; off-sheet AM26x_TDO
AM26x_TMS: R60.1 R313.2 ; off-sheet AM26x_TMS
AM26x_UART0_RXD: J7.9 ; off-sheet AM26x_UART0_RXD
AM26x_UART0_TXD: J7.10 ; off-sheet AM26x_UART0_TXD
DAC_SPI3_CLK: J7.13 ; off-sheet DAC_SPI3_CLK
DAC_SPI3_CS0: J7.16 ; off-sheet DAC_SPI3_CS0
DAC_SPI3_D0: J7.14 ; off-sheet DAC_SPI3_D0
DAC_SPI3_D1: J7.15 ; off-sheet DAC_SPI3_D1
DAC_TCK: J7.4 R314.1 ; off-sheet DAC_TCK
DAC_TDI: J7.5 R316.1 ; off-sheet DAC_TDI
DAC_TDO: J7.6 R315.1 ; off-sheet DAC_TDO
DAC_TMS: J7.3 R313.1 ; off-sheet DAC_TMS
JTAG_RESETn: R40.1 R64.1 ; off-sheet JTAG_RESETn
MCU_I2C0_SCL: J7.12 ; off-sheet MCU_I2C0_SCL
MCU_I2C0_SDA: J7.11 ; off-sheet MCU_I2C0_SDA
MIPI_DETECT: J5.58 R31.2 R260.1
MIPI_TRC_CLK[0]: J5.13 R93.2
MIPI_TRC_DATA_00: J5.17 R96.2
MIPI_TRC_DATA_01: J5.19 R98.2
MIPI_TRC_DATA_02: J5.21 R99.2
MIPI_TRC_DATA_03: J5.23 R100.2
MIPI_TRC_DATA_04: J5.25 R101.2
MIPI_TRC_DATA_05: J5.27 R102.2
MIPI_TRC_DATA_06: J5.29 R103.2
MIPI_TRC_DATA_07: J5.31 R86.1
MIPI_TRC_DATA_08: J5.33 R87.1
MIPI_TRC_DATA_09: J5.35 R88.1
MIPI_TRC_DATA_30: J5.37 R89.1
MIPI_TRC_DATA_31: J5.39 R90.1
MIPI_TRC_DATA_32: J5.41 R91.1
MIPI_TRC_DATA_33: J5.43 R92.1
MIPI_TRC_DATA_34: J5.45 R94.1
MIPI_TRC_DATA_35: J5.47 R95.1
MIPI_TRC_DATA_36: J5.49 R97.1
MIPI_VREF_TRACE: J5.12 R216.2
nRESET: J5.6 R64.2
R_MCU_GPIO119: R93.1 ; off-sheet R_MCU_GPIO119
R_MCU_GPIO120: R96.1 ; off-sheet R_MCU_GPIO120
R_PR0_PRU1_GPIO0: R86.2 ; off-sheet R_PR0_PRU1_GPIO0
R_PR0_PRU1_GPIO1: R87.2 ; off-sheet R_PR0_PRU1_GPIO1
R_PR0_PRU1_GPIO2: R88.2 ; off-sheet R_PR0_PRU1_GPIO2
R_PR0_PRU1_GPIO3: R89.2 ; off-sheet R_PR0_PRU1_GPIO3
R_PR0_PRU1_GPIO4: R103.1 ; off-sheet R_PR0_PRU1_GPIO4
R_PR0_PRU1_GPIO5: R98.1 ; off-sheet R_PR0_PRU1_GPIO5
R_PR0_PRU1_GPIO6: R102.1 ; off-sheet R_PR0_PRU1_GPIO6
R_PR0_PRU1_GPIO8: R101.1 ; off-sheet R_PR0_PRU1_GPIO8
R_PR0_PRU1_GPIO9: R99.1 ; off-sheet R_PR0_PRU1_GPIO9
R_PR0_PRU1_GPIO10: R100.1 ; off-sheet R_PR0_PRU1_GPIO10
R_PR0_PRU1_GPIO11: R92.2 ; off-sheet R_PR0_PRU1_GPIO11
R_PR0_PRU1_GPIO12: R94.2 ; off-sheet R_PR0_PRU1_GPIO12
R_PR0_PRU1_GPIO13: R95.2 ; off-sheet R_PR0_PRU1_GPIO13
R_PR0_PRU1_GPIO14: R97.2 ; off-sheet R_PR0_PRU1_GPIO14
R_PR0_PRU1_GPIO15: R91.2 ; off-sheet R_PR0_PRU1_GPIO15
R_PR0_PRU1_GPIO16: R90.2 ; off-sheet R_PR0_PRU1_GPIO16
RTCK/EXTC: J5.7 R65.2
TCK: J5.3 R61.2 R65.1
TDI: J5.5 R63.2
TDO: J5.4 R62.2
TMS: J5.2 R60.2
VREF_DEBUG: J5.1 R59.1
NetJ5_15: J5.15 R26.2

Not connected (* = marked no-connect by the designer): J5 8* 9* 10* 11* 14* 18* 20* 22* 24* 26* 28* 30* 32* 34* 36* 38* 40* 42* 44* 46* 48* 50* 51* 52* 53* 54* 55* 56* 59* 60*

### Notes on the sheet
- MIPI 60 PIN CONNECTOR
- TRC_DATA6
- TRC_DATA7
- EMULATOR HEADER, DAC HEADER
- TRC_DATA8
- TRC_DATA9
- IO_TGT_V
- TRC_DATA10
- TRC_DATA11
- TRC_CLK
- TRC_DATA12
- (near J7) SPIA_CLK
- (near J7) SPIA_PICO
- TRC_DATA13
- (near J7) SPIA_POCI
- (near J7) SPIA_CS0
- TRC_CTL
- TRC_DATA14
- TRC_DATA0
- TRC_DATA1
- TRC_DATA15
- TRC_DATA2
- TRC_DATA3
- TRC_DATA4
- TRC_DATA5

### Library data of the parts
J5 = CMP-0088387-1: CONN RCPT HI-SPD .5MM 60POS DL; Manufacturer: Samtec; Voltage_V: 175V; AEC Qualified: No; Current_A: 25A; DUT-Pitch_mm: 0.5mm; Standoff Height: 0.407mm; Row_Count: 2; Conn Gender: Female; SizeZ_mm: 3.327mm; ContactFinish: Gold,Nickel; Conn Orientation: Vertical; Is Female: yes
J7 = CMP-0121706-1: Conn Unshrouded HDR 16 POS 2.54mm Solder ST SMT; Manufacturer: Samtec; ContactFinish: Gold,Nickel; Row_Count: 2; AEC Qualified: No; Conn Gender: Male; Conn Orientation: Vertical; SizeZ_mm: 10.16mm; Standoff Height: 1.02mm
R26 R31 R64 = CMP-0065361-1: as R6 on sheet PROC195_DAC
R40 R260 = CMP-0026938-5: as R49 on sheet PROC195_CLK_LED_CURRENT_MON_TEMP_CONN
R59 R216 = CMP-0025951-3: RES, 100, 1%, 0.063 W, AEC-Q200 Grade 0, 0402; Manufacturer: Vishay-Dale; Power_W: 63mW; TempCo: 100 ppm/C; Value_Code: 100R; Value: 100; EIA_Code: E96; SizeX_mm: 1; SizeY_mm: 0.5; SizeZ_mm: 0.6; Value2: 0.063W; AEC Qualified: Y; VDC_V: 50V; AEC Category: Q200; AEC Grade: 0
R60-R63 = CMP-0122104-1: 33 Ohms ±5% 0.1W, 1/10W Chip Resistor 0402 (1005 Metric) Automotive AEC-Q200 Thick Film; Manufacturer: Panasonic; AEC Grade: Grade 0; AEC Qualified: Yes; Power_W: 100mW; SizeZ_mm: 0.4mm; TempCo: 200ppm/°C; VDC_V: 50V; Value: 33
R65 = CMP-0027500-1: RES, 22.0, 1%, 0.05 W, 0201; Manufacturer: Yageo America; Power_W: 50mW; TempCo: 200 ppm/C; Value_Code: 22R0; U/M: EA; Value: 22.0; Res_ohm: 22; SizeX_mm: 0.6; SizeY_mm: 0.3; SizeZ_mm: 0.26; Value2: 0.05W; SizeArea_mm2: 0.18; AEC Qualified: N; VDC_V: 25V; AEC Category: Q200
R86-R95 R97-R103 = CMP-0097633-1: 10 Ohms ±1% 0.125W, 1/8W Chip Resistor 0402 (1005 Metric) Automotive AEC-Q200 Thick Film; Manufacturer: Vishay Dale; AEC Qualified: Yes; TempCo: 100ppm/°C; Power_W: 125mW; SizeZ_mm: 0.4mm; AEC Grade: Grade 0; VDC_V: 75V
R96 R313-R316 = CMP-0002710-1: as R3 on sheet PROC195_CLK_LED_CURRENT_MON_TEMP_CONN

## Sheet PROC195_EVM_Hardware.SchDoc
size 431 x 279 mm; Date: Not shown in title block; ApprovedBy: Not shown in title block; CheckedBy: Not shown in title block; Author: Not shown in title block; CompanyName: Not shown in title block; Engineer: Not shown in title block; Organization: Not shown in title block; Address1: Not shown in title block; Address2: Not shown in title block; Address3: Not shown in title block; Address4: Not shown in title block; DocumentNumber: 11; Revision: Use project parameter SCH_Rev; SheetNumber: 18; SheetTotal: 18; PageSetup: Record=PageOptions¦CenterHorizontal=True¦CenterVertical=True¦PrintScale=1.00¦XCorrection=1.00¦YCorrection=1.00¦PrintKind=0¦BorderSize=5000000¦LeftOffset=0¦BottomOffset=0¦Orientation=2¦PaperLength=1000¦PaperWidth=1000¦Scale=100¦PaperSource=15¦PrintQuality=600¦MediaType=1¦DitherType=10¦PaperKind=Letter¦PrintScaleMode=1
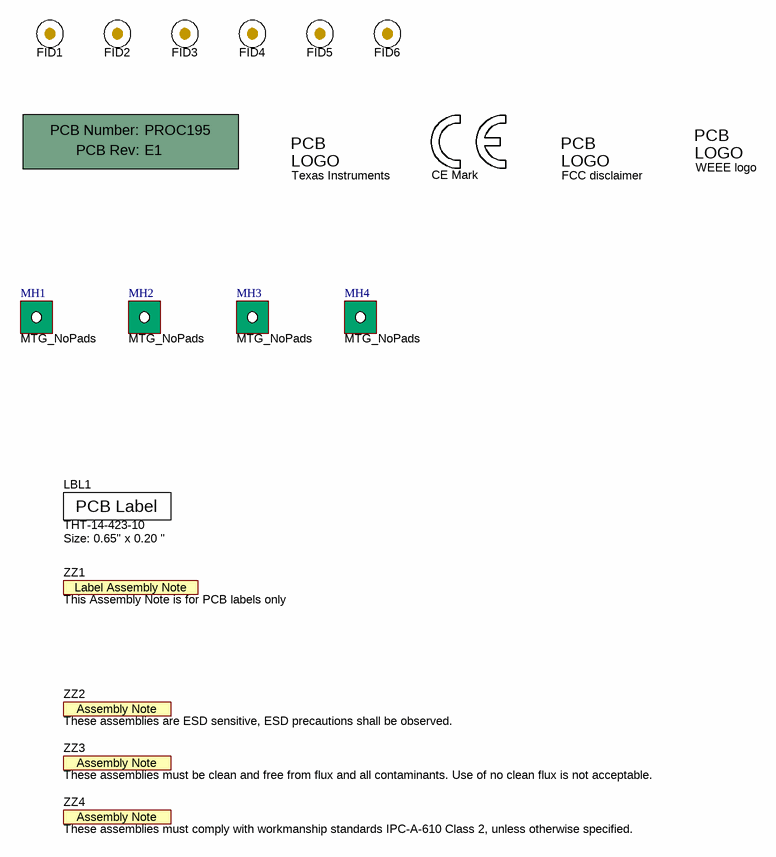
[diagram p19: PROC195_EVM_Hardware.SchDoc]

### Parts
!PCB1  Printed Circuit Board  (value not drawn)  (mechanical)
FID1  Fiducial  [Fiducial10-20]  (value not drawn)
FID2  Fiducial  [Fiducial10-20]  (value not drawn)
FID3  Fiducial  [Fiducial10-20]  (value not drawn)
FID4  Fiducial  [Fiducial10-20]  (value not drawn)
FID5  Fiducial  [Fiducial10-20]  (value not drawn)
FID6  Fiducial  [Fiducial10-20]  (value not drawn)
LBL1  THT-14-423-10  Note: Size: 0.65" x 0.20 "  [Label_650x200]
Logo1  CE Mark  [CE_Mark_5mm]  (no BOM)
Logo2  Texas Instruments  [TI_Stacked_Overlay_Small]  (no BOM)
Logo3  FCC disclaimer  [FCC_disclaimer]  (no BOM)
Logo4  WEEE logo  [WEEE_Minimum]  (no BOM)
MH1  MTG_NoPads  [MTG_159mil]  (no BOM)
MH2  MTG_NoPads  [MTG_159mil]  (no BOM)
MH3  MTG_NoPads  [MTG_159mil]  (no BOM)
MH4  MTG_NoPads  [MTG_159mil]  (no BOM)
ZZ1  This Assembly Note is for PCB labels only  [AssemblyNoteLabel]  (no BOM)
ZZ2  These assemblies are ESD sensitive, ESD precautions shall be observed.  [AssemblyNote]  (no BOM)
ZZ3  These assemblies must be clean and free from flux and all contaminants. Use of no clean flux is not acceptable.  [AssemblyNote]  (no BOM)
ZZ4  These assemblies must comply with workmanship standards IPC-A-610 Class 2, unless otherwise specified.  [AssemblyNote]  (no BOM)

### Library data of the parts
!PCB1 = CMP-0003618-2: Manufacturer: Any; PartNumber: PROC195
FID1-FID6 = CMP-0077181-1: Fiducial mark.  There is nothing to buy or mount.
LBL1 = CMP-0003625-1: Thermal Transfer Printable Labels, 0.650" W x 0.200" H - 10,000 per roll; Manufacturer: Brady
Logo1 = CMP-0074844-1: SymbolCreator: a0412235
Logo2 = CMP-0074838-1: Texas Instrument Corporate Signature; SymbolCreator: a0412235; Lib Reference: TI_Logo; Library Reference: Logo
Logo3 = CMP-0074847-1: FCC_disclaimer
Logo4 = CMP-0074769-3: Manufacturer: Texas Instruments; AEC Category: Q200; CompType: IC
MH1-MH4 = CMP-0078424-2: PCB Mounting Hole, No Pad; Manufacturer: Any; Key: Mounting Hole (non-standard) No Pad
ZZ1 = CMP-0003616-3
ZZ2 = CMP-0077236-1
ZZ3 = CMP-0077237-1
ZZ4 = CMP-0077238-1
